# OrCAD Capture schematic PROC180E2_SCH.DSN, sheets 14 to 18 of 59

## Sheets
14 15. SOC POWER SUPPLIES - LDOs: size C; title: SOC POWER SUPPLIES - LDOs  & VCC_3V3_SYS LOAD SWITCH
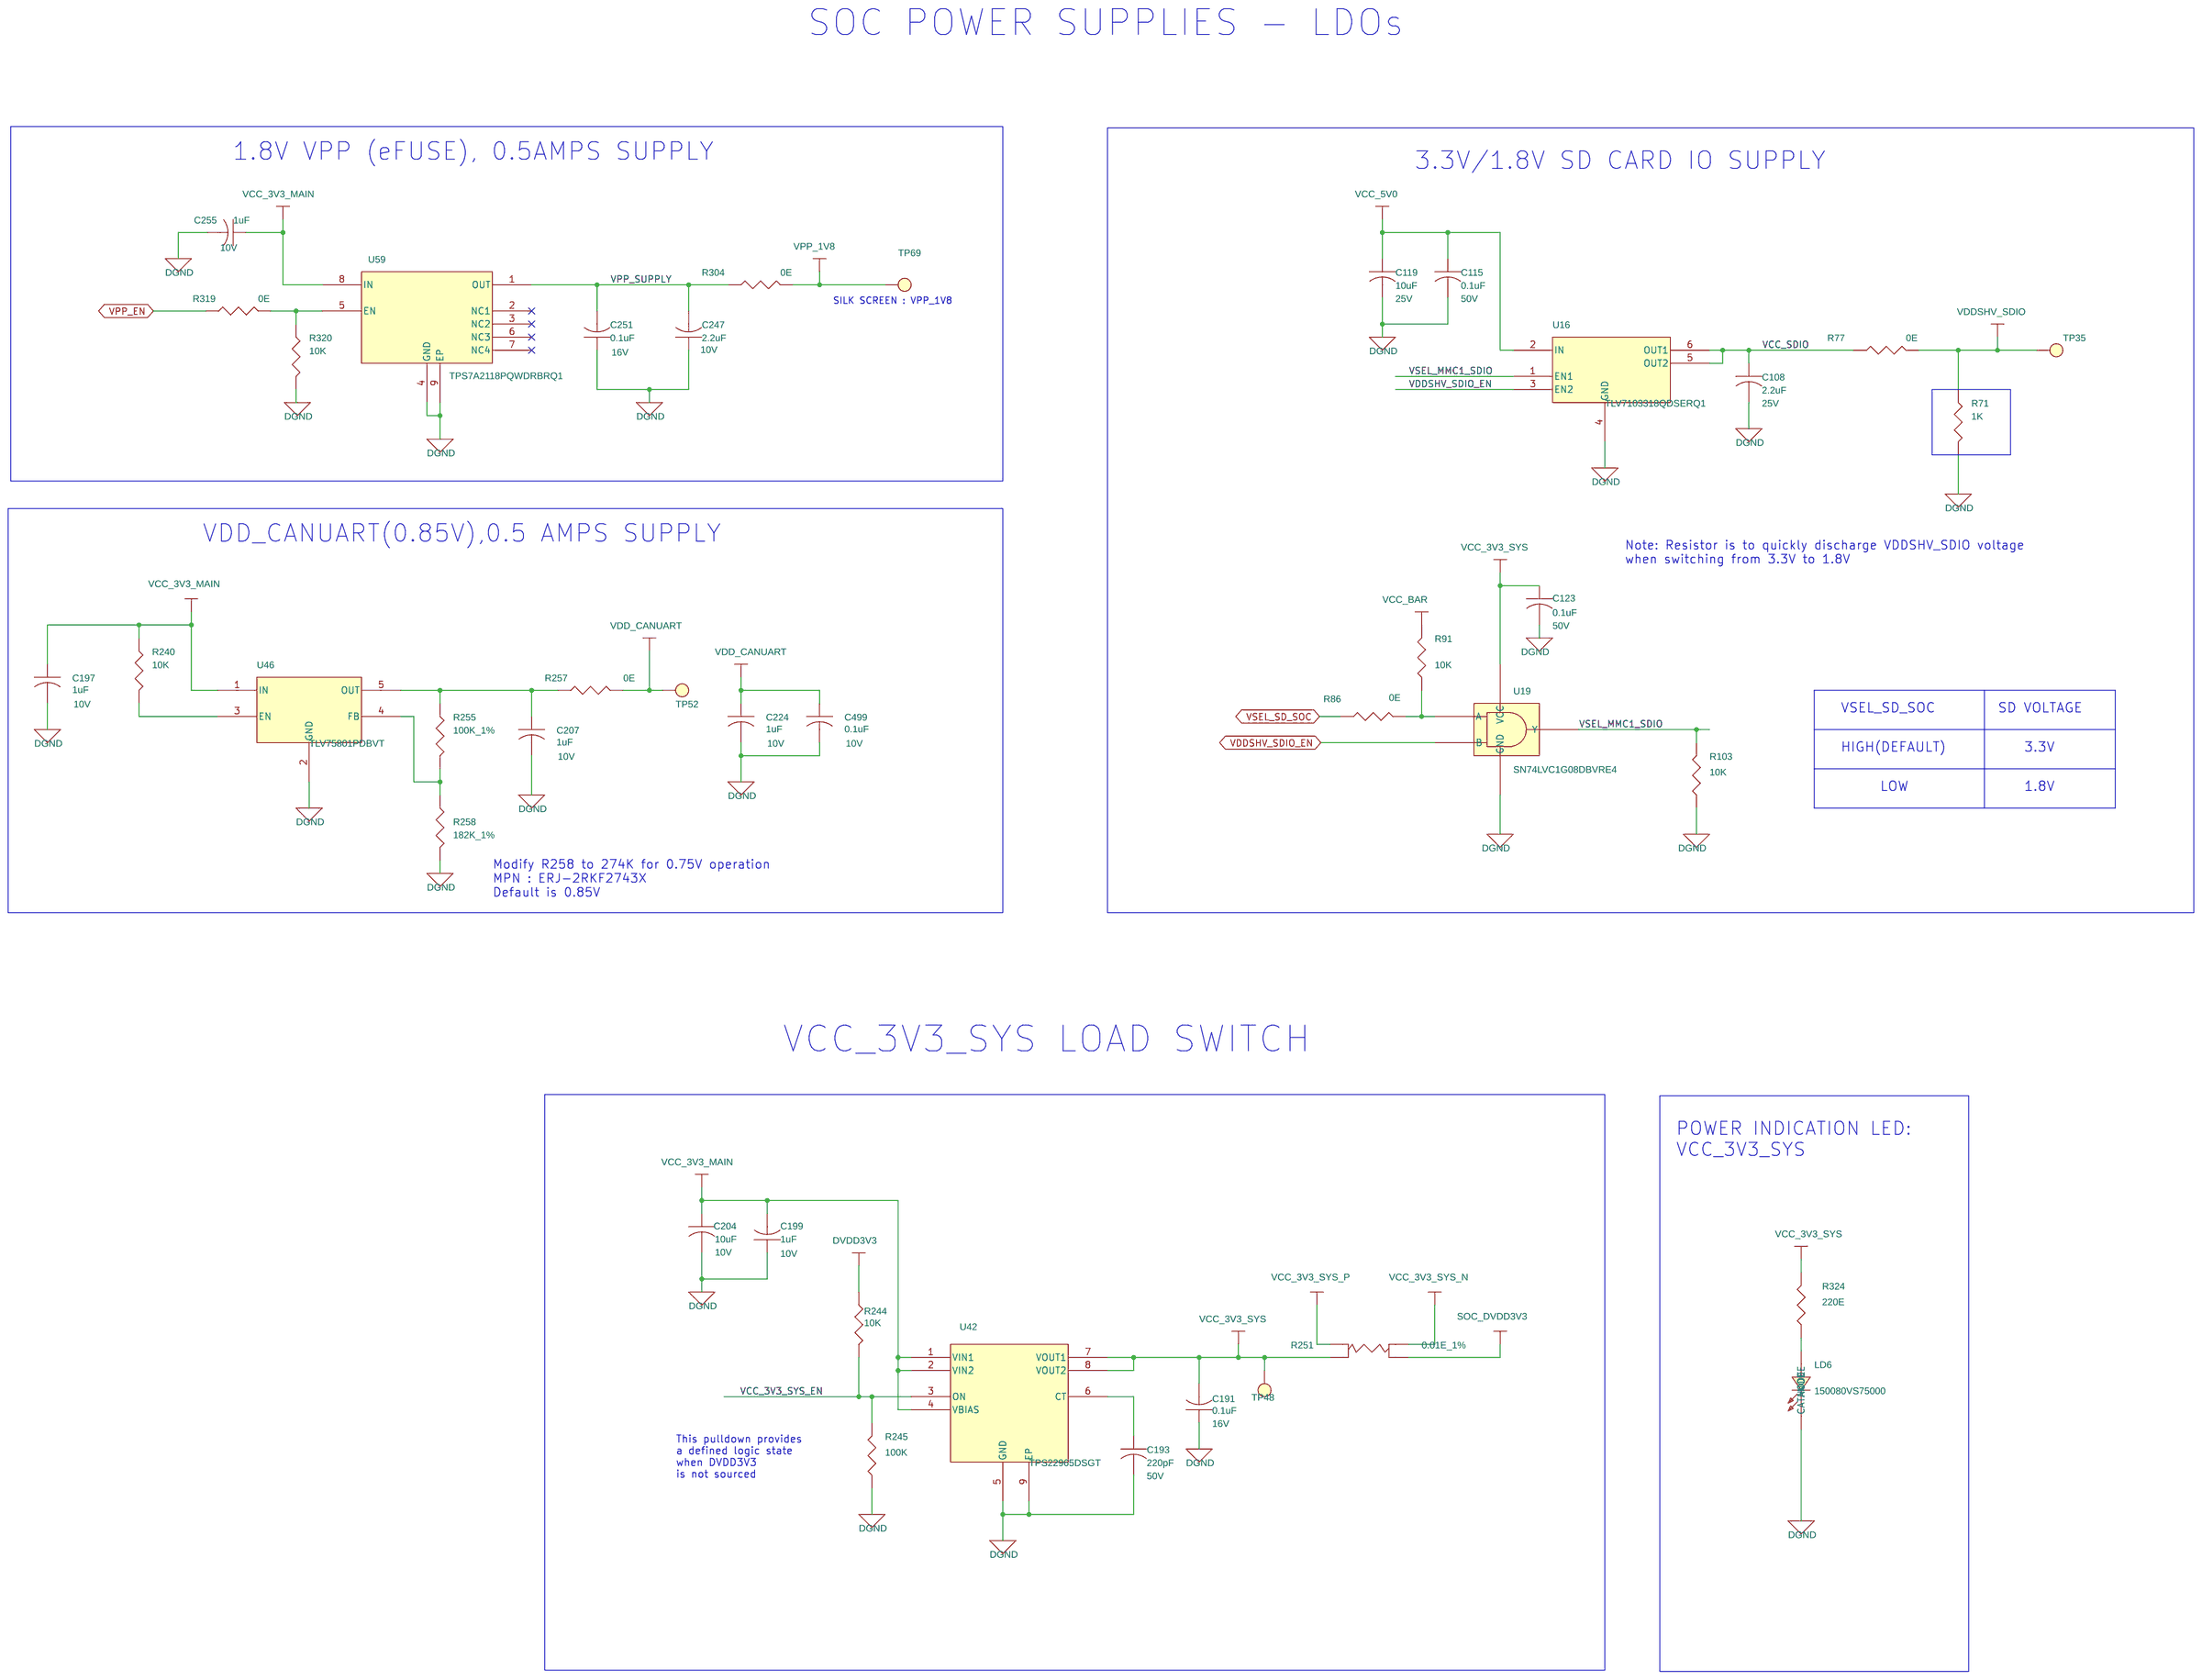
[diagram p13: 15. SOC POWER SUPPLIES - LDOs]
15 03. KEY COLLATERAL REFERENCES: title: LINK TO DESIGN COLLATERALS
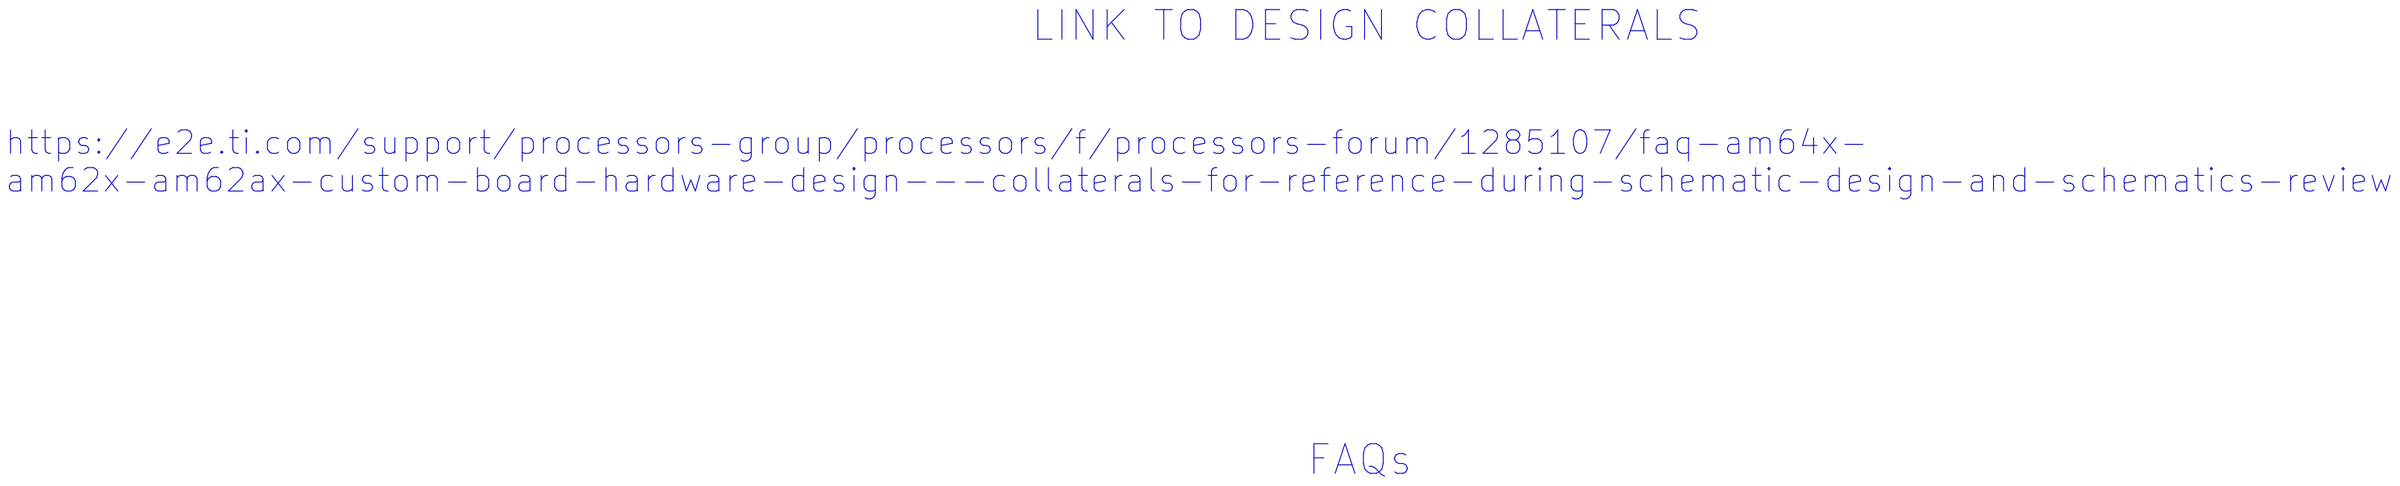
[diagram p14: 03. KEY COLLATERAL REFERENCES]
16 44. PCM6240 BUFFERS: size C; title: PCM6240 BUFFERS
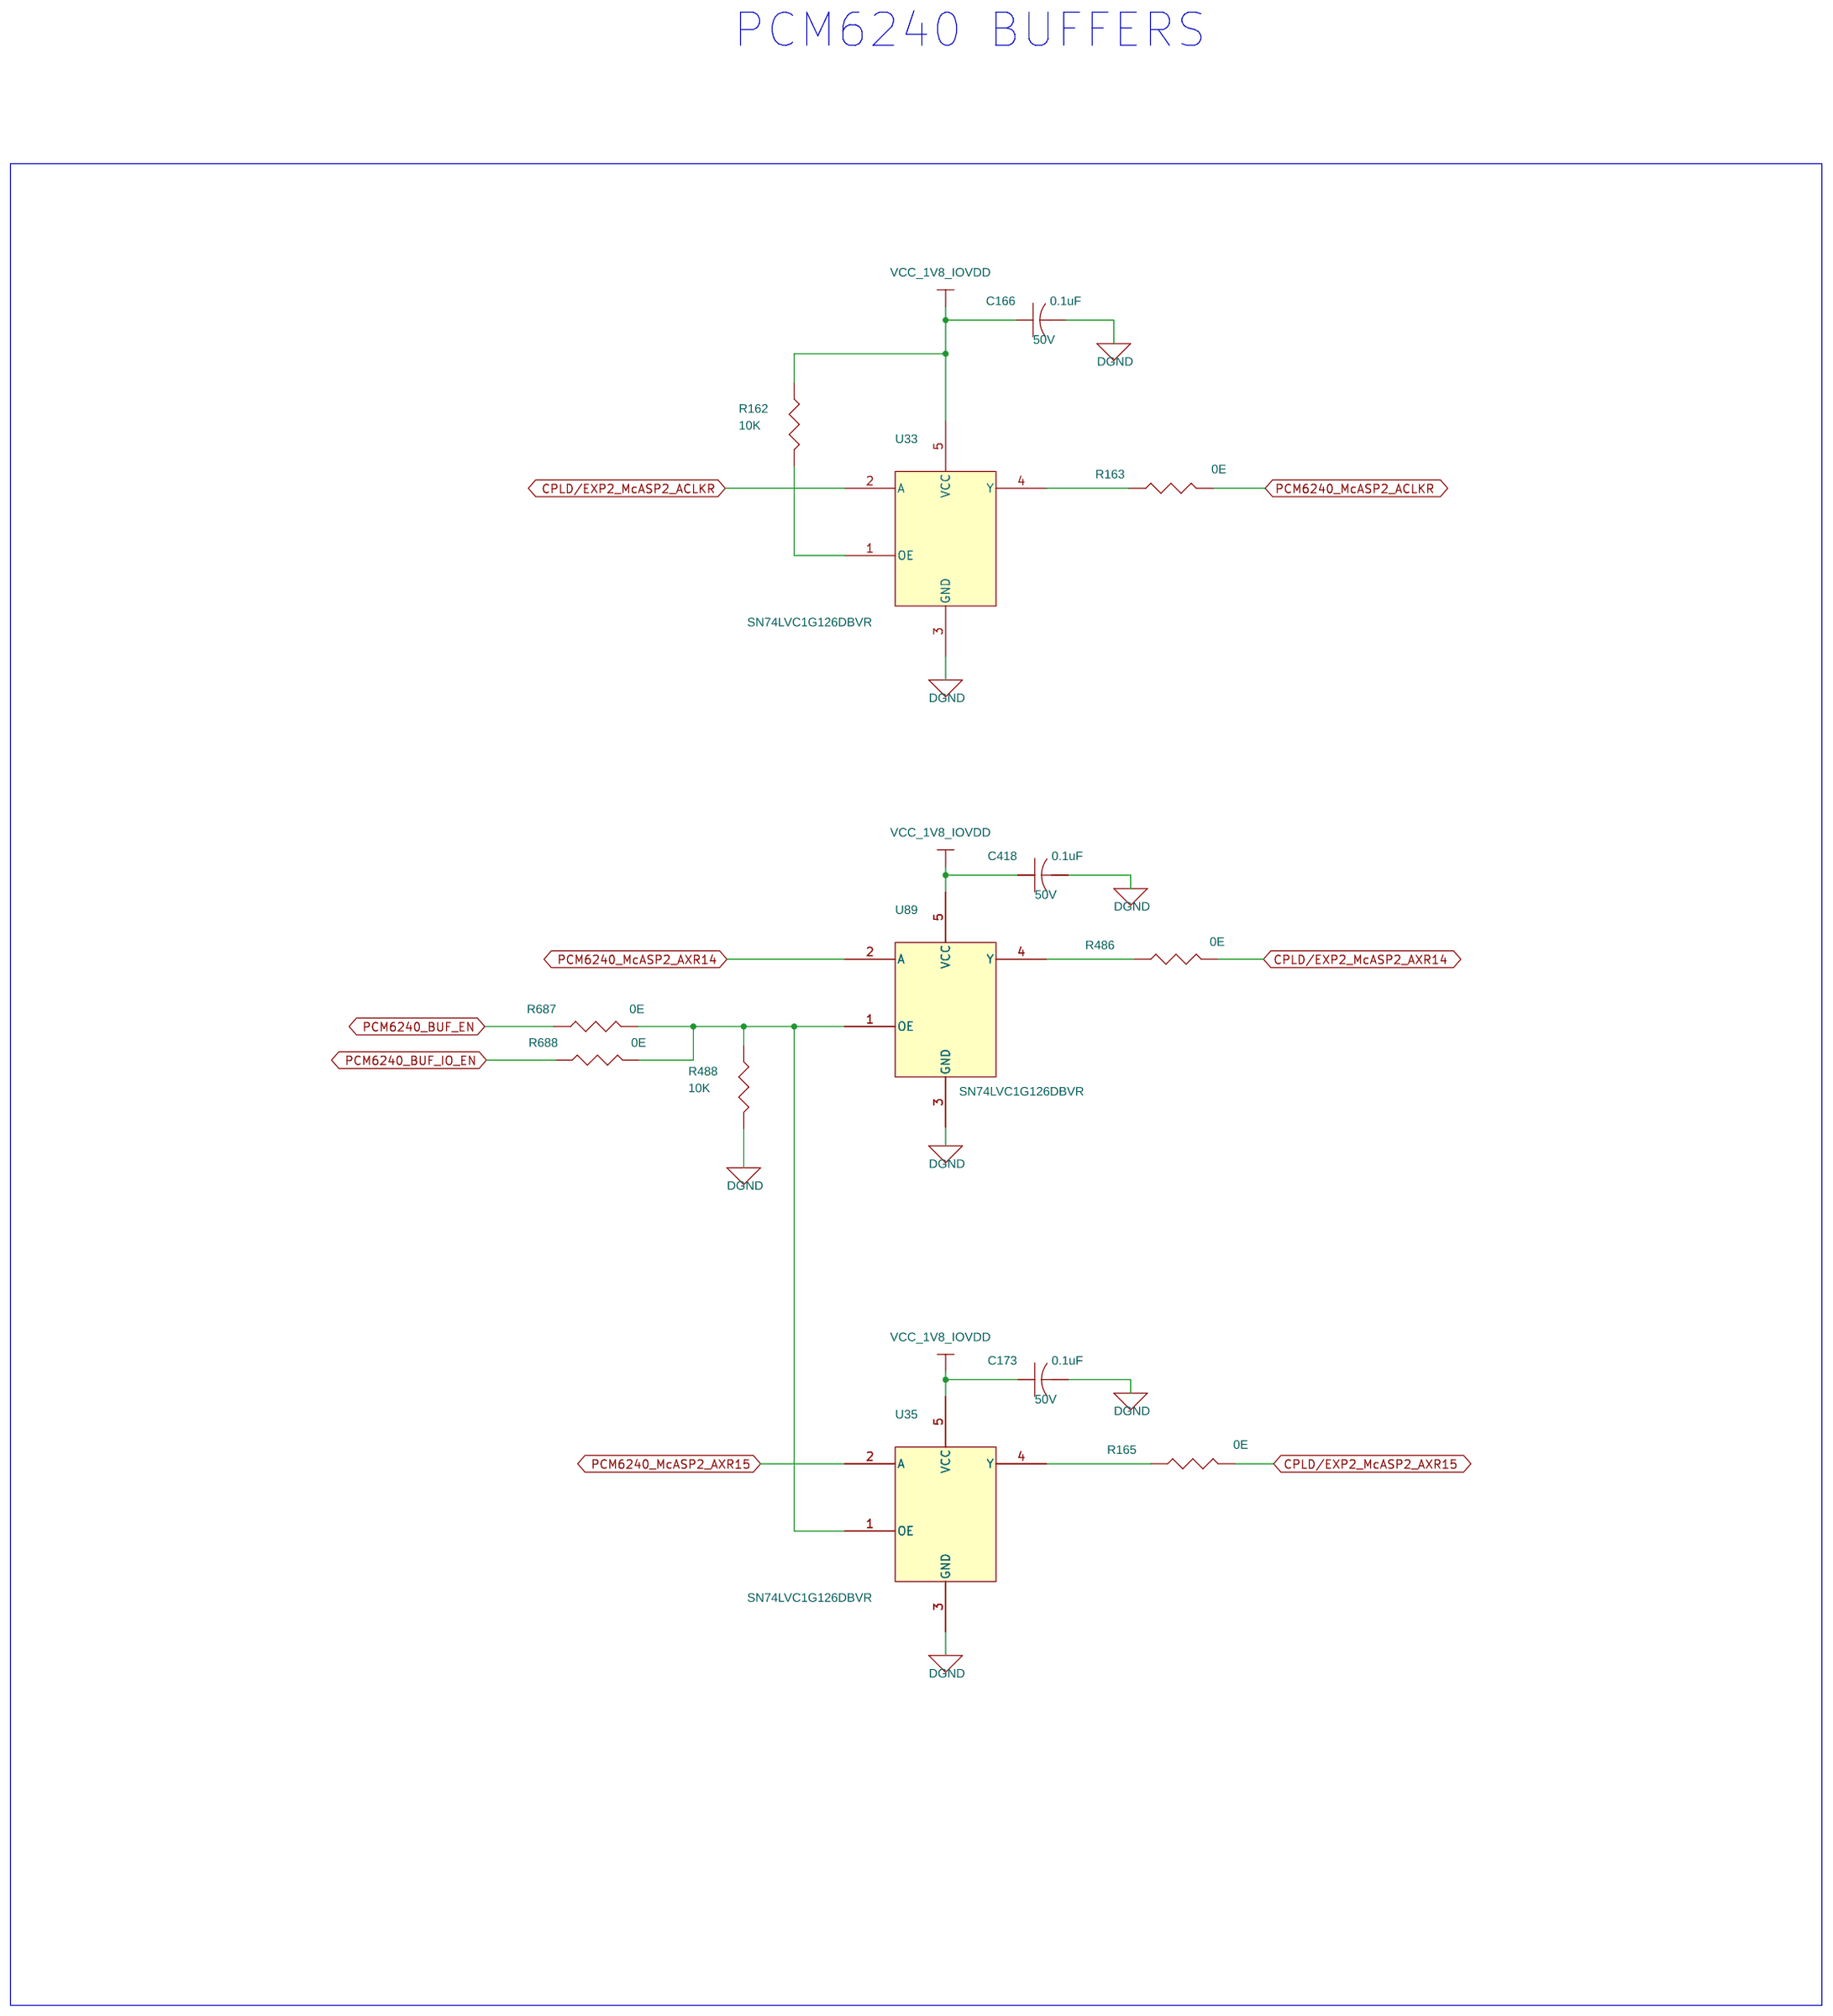
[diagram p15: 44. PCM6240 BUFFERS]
17 50. TEMPERATURE SENSOR & BRD ID: size C; title: TEMPERATURE SENSORS & BOARD ID EEPROM
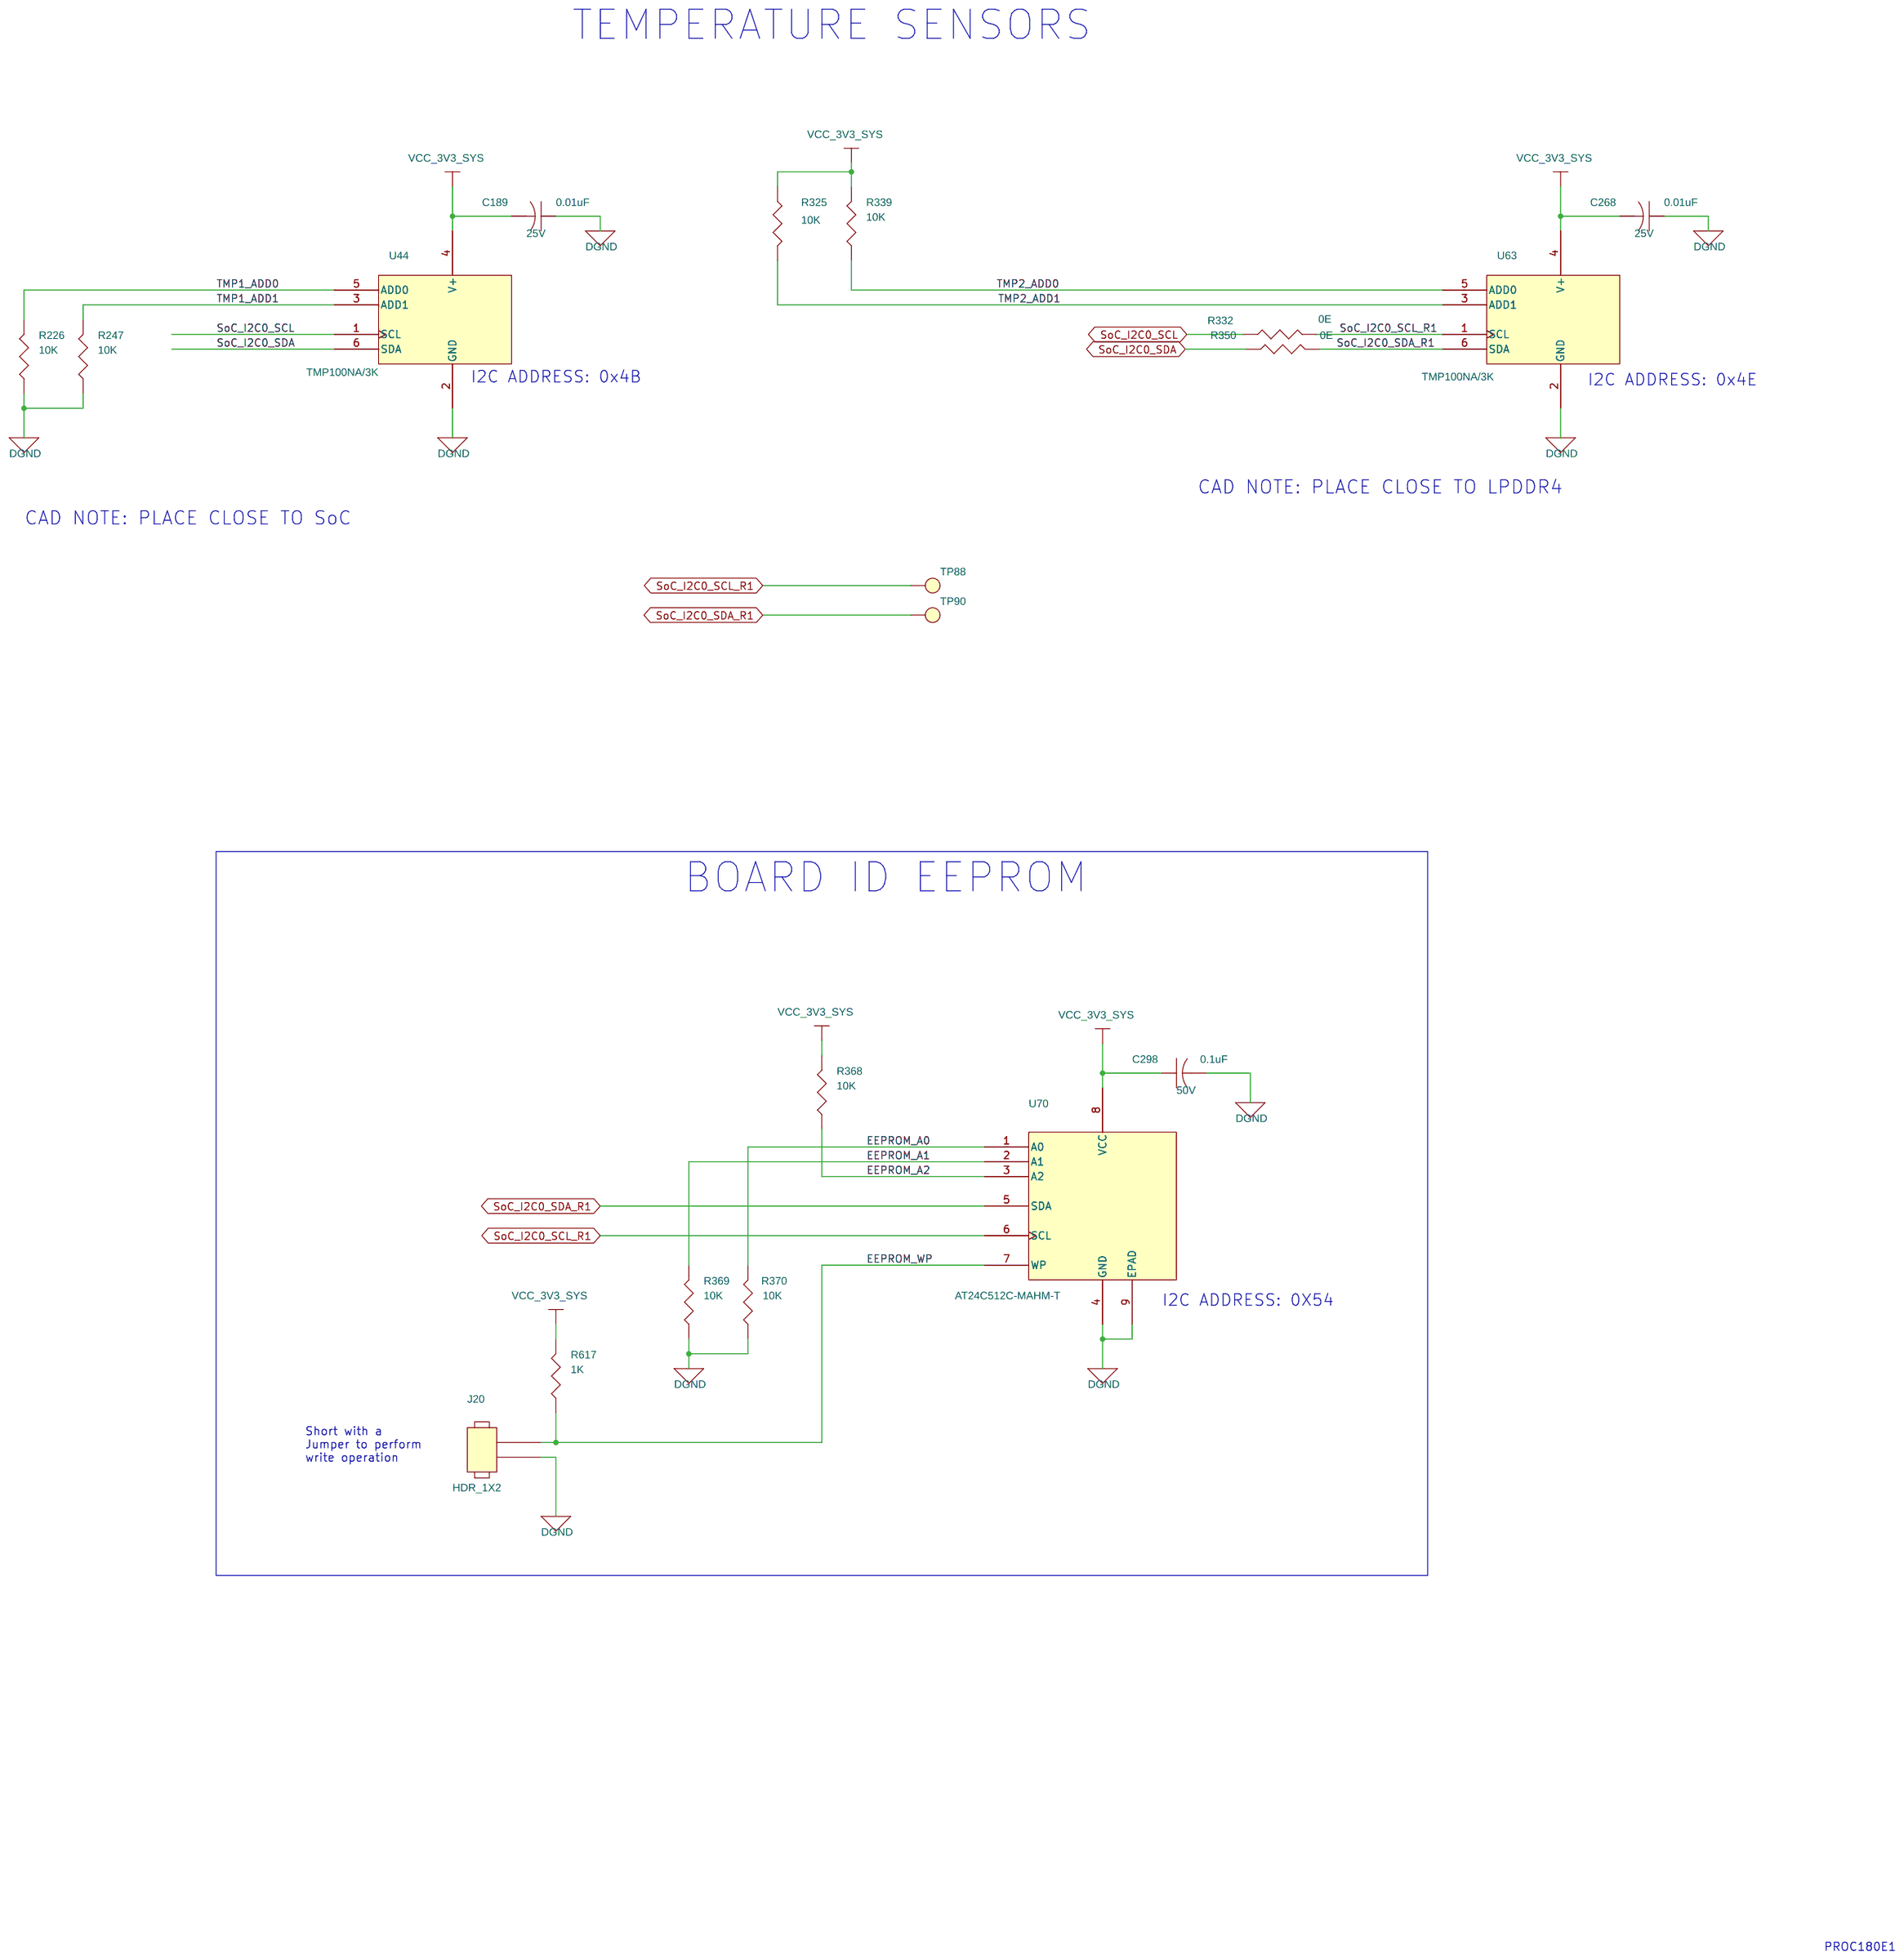
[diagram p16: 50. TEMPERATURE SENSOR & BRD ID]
18 51. CURRENT MONITORING - 1: size C; title: CURRENT MONITORING DEVICES - 1
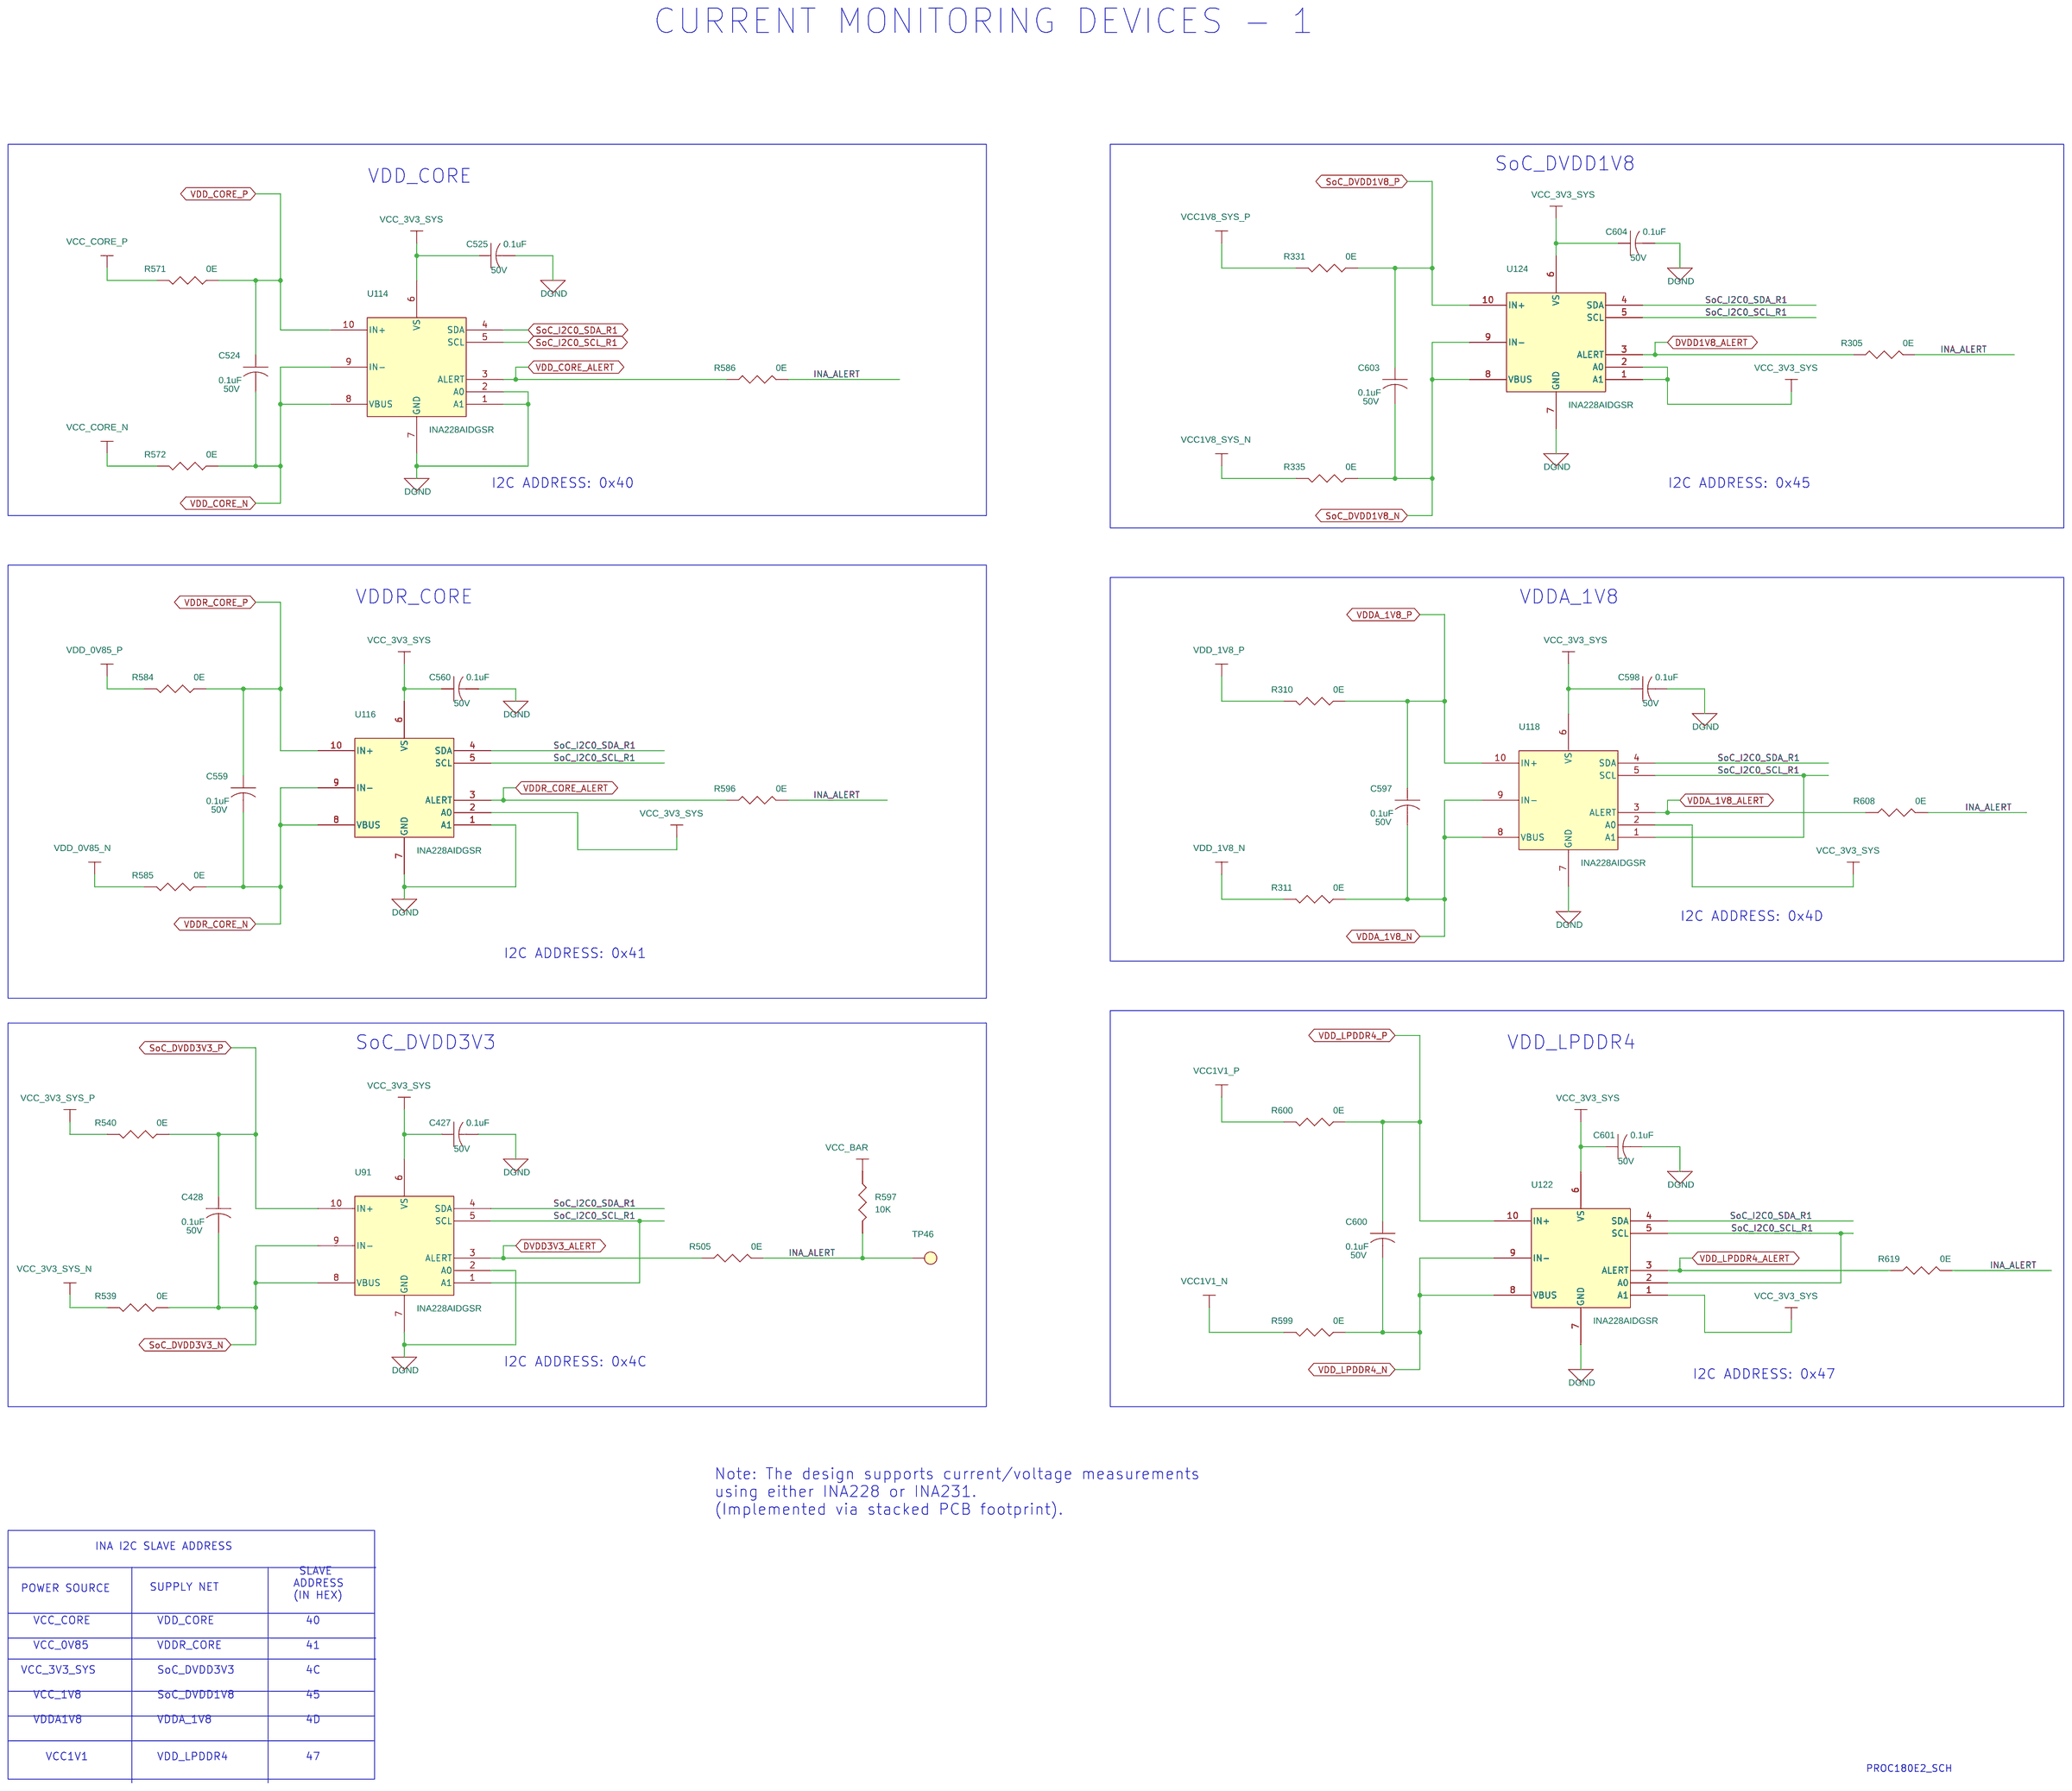
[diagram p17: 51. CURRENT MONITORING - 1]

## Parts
sheet 15. SOC POWER SUPPLIES - LDOs
C108  2.2uF  [CAP0402_0-75]
C115  0.1uF  [CAP0402_0-75]
C119  10uF  [CAP0603_1]
C123  0.1uF  [CAP0402_0-75]
C191  0.1uF  [CAP0201_0-5]
C193  220pF  [CAP0402_0-75]
C197  1uF  [CAP0201_0-5]
C199  1uF  [CAP0201_0-5]
C204  10uF  [CAP0402_0-75]
C207  1uF  [CAP0201_0-5]
C224  1uF  [CAP0201_0-5]
C247  2.2uF  [CAP0201_0-75]
C251  0.1uF  [CAP0201_0-5]
C255  1uF  [CAP0201_0-5]
C499  0.1uF  [CAP0201_0-5]
LD6  150080VS75000  [LED_150080VS75000_80X50_SMD_0-8]
R71  1K  [RES0402_0-5]
R77  0E  [RES0805_0-75]
R86  0E  [RES0805_0-75]
R91  10K  [RES0201_0-5]
R103  10K  [RES0402_0-5]
R240  10K  [RES0201_0-5]
R244  10K  [RES0201_0-5]
R245  100K  [RES0402_0-5]
R251  0.01E_1%  [RES_KRL3216T4_1206-4_0-7]
R255  100K_1%  [RES0402_0-5]
R257  0E  [RES0402_0-5]
R258  182K_1%  [RES0402_0-5]
R304  0E  [RES0603_0-75]
R319  0E  [RES0201_0-5]
R320  10K  [RES0201_0-5]
R324  220E  [RES0402_0-5]
TP35  TP20_SMD  [TP20_SMD]
TP48  TP20_SMD  [TP20_SMD]
TP52  TP20_SMD  [TP20_SMD]
TP69  TP20_SMD  [TP20_SMD]
U16  TLV7103318QDSERQ1  [WSON6_TPS717_60X60_0-8]
U19  SN74LVC1G08DBVRE4  [SOT23-5]
U42  TPS22965DSGT  [WSON8_19-68_80X80_0-8]
U46  TLV75801PDBVT  [SOT23-5_1-5]
U59  TPS7A2118PQWDRBRQ1  [SON8_25-59_130X130_1]
sheet 44. PCM6240 BUFFERS
C166  0.1uF  [CAP0402_0-75]
C173  0.1uF  [CAP0402_0-75]
C418  0.1uF  [CAP0402_0-75]
R162  10K  [RES0201_0-5]
R163  0E  [RES0201_0-5]
R165  0E  [RES0201_0-5]
R486  0E  [RES0201_0-5]
R488  10K  [RES0201_0-5]
R687  0E  [RES0201_0-5]
R688  0E  [RES0201_0-5]
U33  SN74LVC1G126DBVR  [SOT23-5_1-5]
U35  SN74LVC1G126DBVR  [SOT23-5_1-5]
U89  SN74LVC1G126DBVR  [SOT23-5_1-5]
sheet 50. TEMPERATURE SENSOR & BRD ID
C189  0.01uF  [CAP0201_0-5]
C268  0.01uF  [CAP0201_0-5]
C298  0.1uF  [CAP0402_0-75]
J20  HDR_1X2  [HDR_1X2_61300211121_S_T_8-6]
R226  10K  [RES0201_0-5]
R247  10K  [RES0201_0-5]
R325  10K  [RES0201_0-5]
R332  0E  [RES0402_0-5]
R339  10K  [RES0201_0-5]
R350  0E  [RES0402_0-5]
R368  10K  [RES0201_0-5]
R369  10K  [RES0201_0-5]
R370  10K  [RES0201_0-5]
R617  1K  [RES0402_0-5]
TP88  TP20_SMD  [TP20_SMD]
TP90  TP20_SMD  [TP20_SMD]
U44  TMP100NA/3K  [SOT23-6_1-5]
U63  TMP100NA/3K  [SOT23-6_1-5]
U70  AT24C512C-MAHM-T  [UDFN8_19-68_120X80_0-6]
sheet 51. CURRENT MONITORING - 1
C427  0.1uF  [CAP0402_0-75]
C428  0.1uF  [CAP0402_0-75]
C524  0.1uF  [CAP0402_0-75]
C525  0.1uF  [CAP0402_0-75]
C559  0.1uF  [CAP0402_0-75]
C560  0.1uF  [CAP0402_0-75]
C597  0.1uF  [CAP0402_0-75]
C598  0.1uF  [CAP0402_0-75]
C600  0.1uF  [CAP0402_0-75]
C601  0.1uF  [CAP0402_0-75]
C603  0.1uF  [CAP0402_0-75]
C604  0.1uF  [CAP0402_0-75]
R305  0E  [RES0201_0-5]
R310  0E  [RES0402_0-5]
R311  0E  [RES0402_0-5]
R331  0E  [RES0402_0-5]
R335  0E  [RES0402_0-5]
R505  0E  [RES0201_0-5]
R539  0E  [RES0402_0-5]
R540  0E  [RES0402_0-5]
R571  0E  [RES0402_0-5]
R572  0E  [RES0402_0-5]
R584  0E  [RES0402_0-5]
R585  0E  [RES0402_0-5]
R586  0E  [RES0201_0-5]
R596  0E  [RES0201_0-5]
R597  10K  [RES0201_0-5]
R599  0E  [RES0402_0-5]
R600  0E  [RES0402_0-5]
R608  0E  [RES0201_0-5]
R619  0E  [RES0201_0-5]
TP46  TP20_SMD  [TP20_SMD]
U91  INA228AIDGSR  [MSOP10_19-68_120X120_1-1]
U114  INA228AIDGSR  [MSOP10_19-68_120X120_1-1]
U116  INA228AIDGSR  [MSOP10_19-68_120X120_1-1]
U118  INA228AIDGSR  [MSOP10_19-68_120X120_1-1]
U122  INA228AIDGSR  [MSOP10_19-68_120X120_1-1]
U124  INA228AIDGSR  [MSOP10_19-68_120X120_1-1]

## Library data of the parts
C108 = CAP: CAP CERAMIC 2.2uF 25V 10% X5R AUTO 0402; Chkd/date: MANIRAJA/240920; Crtd /date: ALVY/240920; Custom_Duty: 15%; Customs_HS_Code: 85322990; Distributor_name: DIGIKEY; Distributor_part_number: 490-12267-1-ND; Footprint Path: Y:\MIS_DATABASE\Library\ALTIUM_TOOL\PCB_FOOTPRINTS\Altium_Footprint_Lib.PcbLib; Height: 0.70MM; Library Path: Y:\MIS_DATABASE\Library\ALTIUM_TOOL\SCHEMATICS_PARTS\MS_DISCRETE_Library.schlib; Mfr_name: MURATA; Mfr_part_number: GRT155R61E225KE13D; Mistral Part No: 120020090019-R; Package: 0402; Part_type: CAPACITORS\CERAMIC; Project: ECU_RO; RoHS: RoHS; Temperature: -55°C+85°C; Tolerance: 10%; Voltage: 25V; Wattage: NA; Weight: 0.65mg; Datasheet: Y:\MIS_DATABASE\DATASHEETS\CAPACITORS\GRT155R61E225KE13.PDF
C115 C166 C173 C418 = CAP: CAP CERAMIC 0.1uF 50V 10% X7R AUTO 0402; Chkd/date: MANIRAJA/250221; Crtd /date: ALVY/240221; Custom_Duty: 15%; Customs_HS_Code: 85322990; Distributor_name: MOUSER; Distributor_part_number: 81-GRT155R71H104KE1D; Footprint Path: Y:\MIS_DATABASE\Library\ALTIUM_TOOL\PCB_FOOTPRINTS\Altium_Footprint_Lib.PcbLib; Height: 0.55MM; Library Path: Y:\MIS_DATABASE\Library\ALTIUM_TOOL\SCHEMATICS_PARTS\MS_DISCRETE_Library.schlib; Mfr_name: MURATA; Mfr_part_number: GRT155R71H104KE01D; Mistral Part No: 120019030005-R; Package: 0402; Part_type: CAPACITORS\CERAMIC; Project: TI_DRA821 SK EVM BRD; RoHS: RoHS; Temperature: -55°C+125°C; Tolerance: 10%; Voltage: 50V; Wattage: NA; Weight: NA; Datasheet: Y:\MIS_DATABASE\DATASHEETS\CAPACITORS\GRT155R71H104KE01.PDF
C119 = CAP: CAP CERAMIC 10uF 25V 20% X5R AUTO 0603; Chkd/date: PRADEEP/130623; Crtd /date: PRADEEP/130623; Custom_Duty: 15%; Customs_HS_Code: 85322990; Distributor_name: NA; Distributor_part_number: NA; Footprint Path: Y:\MIS_DATABASE\Library\ALTIUM_TOOL\PCB_FOOTPRINTS\Altium_Footprint_Lib.PcbLib; Height: 1.00MM; Library Path: Y:\MIS_DATABASE\Library\ALTIUM_TOOL\SCHEMATICS_PARTS\MS_DISCRETE_Library.schlib; Mfr_name: MURATA; Mfr_part_number: GRT188R61E106ME13; Mistral Part No: 120022060023-R; Package: 0603; Part_type: CAPACITORS\CERAMIC; Project: AM62P_SK; RoHS: RoHS; Temperature: -55°C+85°C; Tolerance: 20%; Voltage: 25V; Wattage: NA; Weight: 2mg; Datasheet: Y:\MIS_DATABASE\DATASHEETS\CAPACITORS\GRT188R61E106ME13.PDF
C123 C298 C427 C428 C524 C525 C559 C560 C597 C598 C600 C601 C603 C604 = CAP: CAP CERAMIC 0.1uF 50V 10% X7R AUTO 0402; Alt_Mfr_name: YAGEO AMERICA; Alt_Mfr_part_number: CC0402KRX5R8BB104; Chkd/date: MANIRAJA/250221; Crtd /date: ALVY/240221; Custom_Duty: 15%; Customs_HS_Code: 85322990; Distributor_name: MOUSER; Distributor_part_number: 81-GRT155R71H104KE1D; Footprint Path: Y:\MIS_DATABASE\Library\ALTIUM_TOOL\PCB_FOOTPRINTS\Altium_Footprint_Lib.PcbLib; Height: 0.55MM; Library Path: Y:\MIS_DATABASE\Library\ALTIUM_TOOL\SCHEMATICS_PARTS\MS_DISCRETE_Library.schlib; Mfr_name: MURATA; Mfr_part_number: GRT155R71H104KE01D; Mistral Part No: 120019030005-R; Package: 0402; Part_type: CAPACITORS\CERAMIC; Project: TI_DRA821 SK EVM BRD; RoHS: RoHS; Temperature: -55°C+125°C; Tolerance: 10%; Voltage: 50V; Wattage: NA; Weight: NA; Datasheet: Y:\MIS_DATABASE\DATASHEETS\CAPACITORS\GRT155R71H104KE01.PDF
C191 C251 = CAP: CAP CERAMIC 0.1uF 16V 10% X7S AUTO 0201; Alt_Mfr_name: YAGEO AMERICA; Alt_Mfr_part_number: CC0402KRX5R8BB104; Chkd/date: MANIRAJA/110321; Crtd /date: ALVY/110321; Custom_Duty: 15%; Customs_HS_Code: 85322990; Distributor_name: DIGIKEY; Distributor_part_number: 490-GRT033C71C104KE01DTR-ND; Footprint Path: Y:\MIS_DATABASE\Library\ALTIUM_TOOL\PCB_FOOTPRINTS\Altium_Footprint_Lib.PcbLib; Height: 0.33MM; Library Path: Y:\MIS_DATABASE\Library\ALTIUM_TOOL\SCHEMATICS_PARTS\MS_DISCRETE_Library.schlib; Mfr_name: MURATA; Mfr_part_number: GRT033C71C104KE01D; Mistral Part No: 120021030007-R; Package: 0201; Part_type: CAPACITORS\CERAMIC; Project: J7ES_SK_BRD; RoHS: RoHS; Temperature: -55°C+125°C; Tolerance: 10%; Voltage: 16V; Wattage: NA; Weight: 330mg; Datasheet: Y:\MIS_DATABASE\DATASHEETS\CAPACITORS\GRT033C71C104KE01.PDF
C193 = CAP: CAP CERAMIC 220pF 50V 5% C0G(NP0) AUTO 0402; Chkd/date: PRADEEP/130623; Crtd /date: PRADEEP/130623; Custom_Duty: 15%; Customs_HS_Code: 85322990; Distributor_name: NA; Distributor_part_number: NA; Footprint Path: Y:\MIS_DATABASE\Library\ALTIUM_TOOL\PCB_FOOTPRINTS\Altium_Footprint_Lib.PcbLib; Height: 0.55MM; Library Path: Y:\MIS_DATABASE\Library\ALTIUM_TOOL\SCHEMATICS_PARTS\MS_DISCRETE_Library.schlib; Mfr_name: MURATA; Mfr_part_number: GRT1555C1H221JA02; Mistral Part No: 120022060024-R; Package: 0402; Part_type: CAPACITORS\CERAMIC; Project: AM62P_SK; RoHS: RoHS; Temperature: -55°C+125°C; Tolerance: 5%; Voltage: 50V; Wattage: NA; Weight: 3.1mg; Datasheet: Y:\MIS_DATABASE\DATASHEETS\CAPACITORS\GRT1555C1H221JA02.PDF
C197 C207 C224 = CAP: CAP CERAMIC 1uF 10V 20% X5R 0201; Chkd/date: NAVEED/070415; Crtd /date: VASANTHA/230314; Custom_Duty: 15%; Customs_HS_Code: 85322990; Distributor_name: DIGIKEY; Distributor_part_number: 1276-1324-1-ND; Footprint Path: Y:\MIS_DATABASE\Library\ALTIUM_TOOL\PCB_FOOTPRINTS\Altium_Footprint_Lib.PcbLib; Height: 0.35MM; Library Path: Y:\MIS_DATABASE\Library\ALTIUM_TOOL\SCHEMATICS_PARTS\MS_DISCRETE_Library.schlib; Mfr_name: SAMSUNG; Mfr_part_number: CL03A105MP3NSNC; Mistral Part No: 120015030003-R; Package: 0201; Part_type: CAPACITORS\CERAMIC; Project: DUET BOARDS; RoHS: RoHS; Temperature: -55°C+85°C; Tolerance: 20%; Voltage: 10V; Wattage: NA; Weight: 0.17mg; Datasheet: Y:\MIS_DATABASE\DATASHEETS\CAPACITORS\CL03A105MP3NSNC.PDF
C199 C255 = CAP: CAP CERAMIC 1uF 10V 20% X6S 0201; Chkd/date: PRADEEP/130623; Crtd /date: PRADEEP/130623; Custom_Duty: 15%; Customs_HS_Code: 85322990; Distributor_name: DIGIKEY; Distributor_part_number: 490-GRT033C81A105ME13DTR-ND; Footprint Path: Y:\MIS_DATABASE\Library\ALTIUM_TOOL\PCB_FOOTPRINTS\Altium_Footprint_Lib.PcbLib; Height: 0.39MM; Library Path: Y:\MIS_DATABASE\Library\ALTIUM_TOOL\SCHEMATICS_PARTS\MS_DISCRETE_Library.schlib; Mfr_name: MURATA; Mfr_part_number: GRT033C81A105ME13D; Mistral Part No: 120022060020-R; Package: 0201; Part_type: CAPACITORS\CERAMIC; Project: AM62P_SK; RoHS: RoHS; Temperature: -55°C+105°C; Tolerance: 20%; Voltage: 10V; Wattage: NA; Weight: NA; Datasheet: Y:\MIS_DATABASE\DATASHEETS\CAPACITORS\GRT033C81A105ME13D.PDF
C204 = CAP: CAP CERAMIC 10uF 10V 20% X5R 0402; Chkd/date: PRADEEP/130623; Crtd /date: PRADEEP/130623; Custom_Duty: 15%; Customs_HS_Code: 85322990; Distributor_name: NA; Distributor_part_number: NA; Footprint Path: Y:\MIS_DATABASE\Library\ALTIUM_TOOL\PCB_FOOTPRINTS\Altium_Footprint_Lib.PcbLib; Height: 0.55MM; Library Path: Y:\MIS_DATABASE\Library\ALTIUM_TOOL\SCHEMATICS_PARTS\MS_DISCRETE_Library.schlib; Mfr_name: MURATA; Mfr_part_number: GRM155R61A106ME18; Mistral Part No: 120022060018-R; Package: 0402; Part_type: CAPACITORS\CERAMIC; Project: AM62P_SK; RoHS: RoHS; Temperature: -55°C+85°C; Tolerance: 20%; Voltage: 10V; Wattage: NA; Weight: 6mg; Datasheet: Y:\MIS_DATABASE\DATASHEETS\CAPACITORS\MURATA-GXX-SER_NOV17.PDF
C247 = CAP: CAP CERAMIC 2.2uF 10V 20% X5R 0201; Chkd/date: PRADEEP/130623; Crtd /date: PRADEEP/130623; Custom_Duty: 15%; Customs_HS_Code: 85322990; Distributor_name: NA; Distributor_part_number: NA; Footprint Path: Y:\MIS_DATABASE\Library\ALTIUM_TOOL\PCB_FOOTPRINTS\Altium_Footprint_Lib.PcbLib; Height: 0.55MM; Library Path: Y:\MIS_DATABASE\Library\ALTIUM_TOOL\SCHEMATICS_PARTS\MS_DISCRETE_Library.schlib; Mfr_name: MURATA; Mfr_part_number: GRM035R61A225ME01; Mistral Part No: 120022060026-R; Package: 0201; Part_type: CAPACITORS\CERAMIC; Project: AM62P_SK; RoHS: RoHS; Temperature: -55°C+85°C; Tolerance: 20%; Voltage: 10V; Wattage: NA; Weight: 0.57mg; Datasheet: Y:\MIS_DATABASE\DATASHEETS\CAPACITORS\GRM035R61A225ME01.PDF
C499 = CAP: CAP CERAMIC 0.1uF 10V 10% X5R 0201; Chkd/date: MANIRAJA/290421; Crtd /date: ALVY/290421; Custom_Duty: 15%; Customs_HS_Code: 85322990; Distributor_name: DIGIKEY; Distributor_part_number: 1276-1115-1-ND; Footprint Path: Y:\MIS_DATABASE\Library\ALTIUM_TOOL\PCB_FOOTPRINTS\Altium_Footprint_Lib.PcbLib; Height: 0.33MM; Library Path: Y:\MIS_DATABASE\Library\ALTIUM_TOOL\SCHEMATICS_PARTS\MS_DISCRETE_Library.schlib; Mfr_name: SAMSUNG; Mfr_part_number: CL03A104KP3NNNC; Mistral Part No: 120009050017-R; Package: 0201; Part_type: CAPACITORS\CERAMIC; Project: SRMS-SAR_BRD; RoHS: RoHS; Temperature: -55°C+85°C; Tolerance: 10%; Voltage: 10V; Wattage: NA; Weight: 0.33mg; Datasheet: Y:\MIS_DATABASE\DATASHEETS\CAPACITORS\CL03A104KP3NNNC.PDF
LD6 = DIODE_LED: DIODE LED BRIGHT GREEN SMD; Chkd/date: MANIRAJA/180820; Crtd /date: ALVY/180820; Custom_Duty: 24%; Customs_HS_Code: 85439000; Distributor_name: DIGIKEY; Distributor_part_number: 732-4986-1-ND; Footprint Path: Y:\MIS_DATABASE\Library\ALTIUM_TOOL\PCB_FOOTPRINTS\Altium_Footprint_Lib.PcbLib; Height: 0.80MM; Library Path: Y:\MIS_DATABASE\Library\ALTIUM_TOOL\SCHEMATICS_PARTS\MS_OPTO_Library.schlib; Mfr_name: WURTH ELECTRONICS; Mistral Part No: 130020080012-R; Package: SMD; Part_type: OPTO\LED; Project: AM64x_EVM_BRD; RoHS: RoHS; Temperature: -40°C+85°C; Tolerance: NA; Voltage: NA; Wattage: NA; Weight: 10mg; Datasheet: Y:\MIS_DATABASE\DATASHEETS\DISCRETES\LEDS\150080VS75000.PDF
R71 R617 = RESISTOR: RES 1K 1/10W 5% 0402; Chkd/date: VASANTHA/201216; Crtd /date: MAZHAR/230805; Custom_Duty: 15%; Customs_HS_Code: 85332119; Distributor_name: DIGIKEY; Distributor_part_number: P1.0KJCT-ND; Footprint Path: Y:\MIS_DATABASE\Library\ALTIUM_TOOL\PCB_FOOTPRINTS\Altium_Footprint_Lib.PcbLib; Height: 0.40MM; Library Path: Y:\MIS_DATABASE\Library\ALTIUM_TOOL\SCHEMATICS_PARTS\MS_DISCRETE_Library.schlib; Mfr_name: PANASONIC-ECG; Mfr_part_number: ERJ-2GEJ102X; Mistral Part No: 110009030400-R; Package: 0402; Part_type: RESISTORS\FIXED; Project: HSE; RoHS: RoHS; Temperature: -55°C+155°C; Tolerance: 5%; Voltage: NA; Wattage: 1/10W; Weight: 0.8mg; Datasheet: Y:\MIS_DATABASE\DATASHEETS\RESISTORS\PAN-ERJSER_NOV17.PDF
R77 R86 = RESISTOR: RES 0E 1/8W 5% 0805; Chkd/date: VASANTHA/130416; Crtd /date: JEBRAN/020316; Custom_Duty: 15%; Customs_HS_Code: 85332119; Distributor_name: DIGIKEY; Distributor_part_number: 311-0.0ARCT-ND; Footprint Path: Y:\MIS_DATABASE\Library\ALTIUM_TOOL\PCB_FOOTPRINTS\Altium_Footprint_Lib.PcbLib; Height: 0.60MM; Library Path: Y:\MIS_DATABASE\Library\ALTIUM_TOOL\SCHEMATICS_PARTS\MS_DISCRETE_Library.schlib; Mfr_name: YAGEO AMERICA; Mfr_part_number: RC0805JR-070RL; Mistral Part No: 110009030074-R; Package: 0805; Part_type: RESISTORS\FIXED; Project: ZK_BIOMETRIC; RoHS: RoHS; Temperature: -55°C+155°C; Tolerance: 5%; Voltage: NA; Wattage: 1/8W; Weight: 5.5mg; Datasheet: Y:\MIS_DATABASE\DATASHEETS\RESISTORS\RCXXXXL-SER_MAR18.PDF
R91 R162 R226 R240 R244 R247 R320 R325 R339 R368-R370 R488 R597 = RESISTOR: RES 10K 1/20W 5% 0201; Chkd/date: MANIRAJA/050517; Crtd /date: MANIRAJA/050517; Custom_Duty: 15%; Customs_HS_Code: 85332119; Distributor_name: DIGIKEY; Distributor_part_number: 311-10KNCT-ND; Footprint Path: Y:\MIS_DATABASE\Library\ALTIUM_TOOL\PCB_FOOTPRINTS\Altium_Footprint_Lib.PcbLib; Height: 0.26MM; Library Path: Y:\MIS_DATABASE\Library\ALTIUM_TOOL\SCHEMATICS_PARTS\MS_DISCRETE_Library.schlib; Mfr_name: YAGEO AMERICA; Mfr_part_number: RC0201JR-0710KL; Mistral Part No: 110010070051-R; Package: 0201; Part_type: RESISTORS\FIXED; Project: GOLDEN-I LITE; RoHS: RoHS; Temperature: -55°C+125°C; Tolerance: 5%; Voltage: NA; Wattage: 1/20W; Weight: 0.17mg; Datasheet: Y:\MIS_DATABASE\DATASHEETS\RESISTORS\RCXXXXL-SER_MAR18.PDF
R103 = RESISTOR: RES 10K 1/16W 5% 0402; Chkd/date: VASANTHA/061216; Crtd /date: MAZHAR/230805; Custom_Duty: 15%; Customs_HS_Code: 85332119; Distributor_name: DIGIKEY; Distributor_part_number: 311-10KJRCT-ND; Footprint Path: Y:\MIS_DATABASE\Library\ALTIUM_TOOL\PCB_FOOTPRINTS\Altium_Footprint_Lib.PcbLib; Height: 0.40MM; Library Path: Y:\MIS_DATABASE\Library\ALTIUM_TOOL\SCHEMATICS_PARTS\MS_DISCRETE_Library.schlib; Mfr_name: YAGEO AMERICA; Mfr_part_number: RC0402JR-0710KL; Mistral Part No: 110011060021-R; Package: 0402; Part_type: RESISTORS\FIXED; Project: HSE; RoHS: RoHS; Temperature: -55°C+155°C; Tolerance: 5%; Voltage: NA; Wattage: 1/16W; Weight: 0.65mg; Datasheet: Y:\MIS_DATABASE\DATASHEETS\RESISTORS\RCXXXXL-SER_MAR18.PDF
R245 = RESISTOR: RES 100K 1/10W 5% 0402; Chkd/date: VASANTHA/291216; Crtd /date: GEETHA/190406; Custom_Duty: 15%; Customs_HS_Code: 85332119; Distributor_name: DIGIKEY; Distributor_part_number: P100KJCT-ND; Footprint Path: Y:\MIS_DATABASE\Library\ALTIUM_TOOL\PCB_FOOTPRINTS\Altium_Footprint_Lib.PcbLib; Height: 0.40MM; Library Path: Y:\MIS_DATABASE\Library\ALTIUM_TOOL\SCHEMATICS_PARTS\MS_DISCRETE_Library.schlib; Mfr_name: PANASONIC-ECG; Mfr_part_number: ERJ-2GEJ104X; Mistral Part No: 110009030177-R; Package: 0402; Part_type: RESISTORS\FIXED; Project: RED EYE; RoHS: RoHS; Temperature: -55°C+155°C; Tolerance: 5%; Voltage: NA; Wattage: 1/10W; Weight: 0.8mg; Datasheet: Y:\MIS_DATABASE\DATASHEETS\RESISTORS\PAN-ERJSER_NOV17.PDF
R251 = RESISTOR-4TERM: RES 0.01E 1W 1% 1206-4; Chkd/date: MANIRAJA/060318; Crtd /date: MANIRAJA/060318; Custom_Duty: 15%; Customs_HS_Code: 85332119; Distributor_name: DIGIKEY; Distributor_part_number: 408-1974-1-ND; Footprint Path: Y:\MIS_DATABASE\Library\ALTIUM_TOOL\PCB_FOOTPRINTS\Altium_Footprint_Lib.PcbLib; Height: 0.70MM; Library Path: Y:\MIS_DATABASE\Library\ALTIUM_TOOL\SCHEMATICS_PARTS\MS_DISCRETE_Library.schlib; Mfr_name: SUSUMU; Mfr_part_number: KRL3216T4A-M-R010-F-T1; Mistral Part No: 110018030003-R; Package: 1206-4; Part_type: RESISTORS\FIXED; Project: GRACO SMART MODULE; RoHS: RoHS; Temperature: -55°C+155°C; Tolerance: 1%; Voltage: NA; Wattage: 1W; Weight: 16.2mg; Datasheet: Y:\MIS_DATABASE\DATASHEETS\RESISTORS\KRL-SERIES.PDF
R255 = RESISTOR: RES 100K 1/10W 1% 0402; Chkd/date: VASANTHA/201216; Crtd /date: MAZHAR/130306; Custom_Duty: 15%; Customs_HS_Code: 85332119; Distributor_name: DIGIKEY; Distributor_part_number: P100KLCT-ND; Footprint Path: Y:\MIS_DATABASE\Library\ALTIUM_TOOL\PCB_FOOTPRINTS\Altium_Footprint_Lib.PcbLib; Height: 0.40MM; Library Path: Y:\MIS_DATABASE\Library\ALTIUM_TOOL\SCHEMATICS_PARTS\MS_DISCRETE_Library.schlib; Mfr_name: PANASONIC-ECG; Mfr_part_number: ERJ-2RKF1003X; Mistral Part No: 110009030187-R; Package: 0402; Part_type: RESISTORS\FIXED; Project: J32; RoHS: RoHS; Temperature: -55°C+155°C; Tolerance: 1%; Voltage: NA; Wattage: 1/10W; Weight: 0.8mg; Datasheet: Y:\MIS_DATABASE\DATASHEETS\RESISTORS\PAN-ERJSER_NOV17.PDF
R257 R332 R350 = RESISTOR: RES 0E 1/10W JUMPER 0402; Chkd/date: VASANTHA/061216; Crtd /date: NAVEED/201014; Custom_Duty: 15%; Customs_HS_Code: 85332119; Distributor_name: DIGIKEY; Distributor_part_number: P0.0JCT-ND; Footprint Path: Y:\MIS_DATABASE\Library\ALTIUM_TOOL\PCB_FOOTPRINTS\Altium_Footprint_Lib.PcbLib; Height: 0.40MM; IBISSP_MODLES: VALUE REPEATING 2 TIME; Library Path: Y:\MIS_DATABASE\Library\ALTIUM_TOOL\SCHEMATICS_PARTS\MS_DISCRETE_Library.schlib; Mfr_name: PANASONIC-ECG; Mfr_part_number: ERJ-2GE0R00X; Mistral Part No: 110018030052-R; Package: 0402; Part_type: RESISTORS\FIXED; Project: AEGIS POM; RoHS: RoHS; Temperature: -55°C+155°C; Tolerance: NA; Voltage: NA; Wattage: 1/10W; Weight: 0.8mg; Datasheet: Y:\MIS_DATABASE\DATASHEETS\RESISTORS\PAN-ERJSER_NOV17.PDF
R258 = RESISTOR: RES 182K 1/16W 1% 0402; Chkd/date: ALVY/210122; Crtd /date: TAMILARASU/210122; Custom_Duty: 15%; Customs_HS_Code: 85332119; Distributor_name: DIGIKEY; Distributor_part_number: YAG3015CT-ND; Footprint Path: Y:\MIS_DATABASE\Library\ALTIUM_TOOL\PCB_FOOTPRINTS\Altium_Footprint_Lib.PcbLib; Height: 0.40MM; Library Path: Y:\MIS_DATABASE\Library\ALTIUM_TOOL\SCHEMATICS_PARTS\MS_DISCRETE_Library.schlib; Mfr_name: YAGEO AMERICA; Mfr_part_number: RC0402FR-07182KL; Mistral Part No: 110022010016-R; Package: 0402; Part_type: RESISTORS\FIXED; Project: DLRL DIGITAL RECEIVER_BRD; RoHS: RoHS; Temperature: -55°C+155°C; Tolerance: 1%; Voltage: NA; Wattage: 1/16W; Weight: 0.65mg; Datasheet: Y:\MIS_DATABASE\DATASHEETS\RESISTORS\RCXXXXL-SER_MAR18.PDF
R304 = RESISTOR: RES 0E 1/10W 5% 0603; Chkd/date: MANIRAJA/051217; Crtd /date: BAVISH/180211; Custom_Duty: 15%; Customs_HS_Code: 85332119; Distributor_name: DIGIKEY; Distributor_part_number: 311-0.0GRCT-ND; Footprint Path: Y:\MIS_DATABASE\Library\ALTIUM_TOOL\PCB_FOOTPRINTS\Altium_Footprint_Lib.PcbLib; Height: 0.55MM; Library Path: Y:\MIS_DATABASE\Library\ALTIUM_TOOL\SCHEMATICS_PARTS\MS_DISCRETE_Library.schlib; Mfr_name: YAGEO AMERICA; Mfr_part_number: RC0603JR-070RL; Mistral Part No: 110011020013-R; Package: 0603; Part_type: RESISTORS\FIXED; Project: KENNEL; RoHS: RoHS; Temperature: -55°C+155°C; Tolerance: 5%; Voltage: NA; Wattage: 1/10W; Weight: 2mg; Datasheet: Y:\MIS_DATABASE\DATASHEETS\RESISTORS\RCXXXXL-SER_MAR18.PDF
R163 R165 R305 R319 R486 R505 R586 R596 R608 R619 R687 R688 = RESISTOR: RES 0E 1/20W 5% 0201; Chkd/date: NAVEED/301214; Crtd /date: MUDDU/120710; Custom_Duty: 15%; Customs_HS_Code: 85332119; Distributor_name: DIGIKEY; Distributor_part_number: 311-0.0NCT-ND; Footprint Path: Y:\MIS_DATABASE\Library\ALTIUM_TOOL\PCB_FOOTPRINTS\Altium_Footprint_Lib.PcbLib; Height: 0.26MM; Library Path: Y:\MIS_DATABASE\Library\ALTIUM_TOOL\SCHEMATICS_PARTS\MS_DISCRETE_Library.schlib; Mfr_name: YAGEO AMERICA; Mfr_part_number: RC0201JR-070RL; Mistral Part No: 110010070067-R; Package: 0201; Part_type: RESISTORS\FIXED; Project: PB_BUGBASE; RoHS: RoHS; Temperature: -55°C+125°C; Tolerance: 5%; Voltage: NA; Wattage: 1/20W; Weight: 0.17mg; Datasheet: Y:\MIS_DATABASE\DATASHEETS\RESISTORS\RCXXXXL-SER_MAR18.PDF
R324 = RESISTOR: RES 220E 1/10W 5% 0402; Chkd/date: VASANTHA/291216; Crtd /date: GEETHA/260406; Custom_Duty: 15%; Customs_HS_Code: 85332119; Distributor_name: DIGIKEY; Distributor_part_number: P220JCT-ND; Footprint Path: Y:\MIS_DATABASE\Library\ALTIUM_TOOL\PCB_FOOTPRINTS\Altium_Footprint_Lib.PcbLib; Height: 0.40MM; Library Path: Y:\MIS_DATABASE\Library\ALTIUM_TOOL\SCHEMATICS_PARTS\MS_DISCRETE_Library.schlib; Mfr_name: PANASONIC-ECG; Mfr_part_number: ERJ-2GEJ221X; Mistral Part No: 110009030506-R; Package: 0402; Part_type: RESISTORS\FIXED; Project: RED EYE; RoHS: RoHS; Temperature: -55°C+155°C; Tolerance: 5%; Voltage: NA; Wattage: 1/10W; Weight: 0.8mg; Datasheet: Y:\MIS_DATABASE\DATASHEETS\RESISTORS\PAN-ERJSER_NOV17.PDF
TP35 TP46 TP48 TP52 TP88 TP90 = TESTPOINT: TESTPOINT CIR 20 SMD; Chkd/date: SHREESHAIL/171006; Crtd /date: MAZHAR/171006; Custom_Duty: NA; Customs_HS_Code: NA; Distributor_name: NA; Distributor_part_number: NA; Footprint Path: Y:\MIS_DATABASE\Library\ALTIUM_TOOL\PCB_FOOTPRINTS\Altium_Footprint_Lib.PcbLib; Height: NA; Library Path: Y:\MIS_DATABASE\Library\ALTIUM_TOOL\SCHEMATICS_PARTS\MS_DISCRETE_Library.schlib; MECHANICAL 3D STEP FILE: NA; Mfr_name: LOCAL; Mistral Part No: NA; Package: SMD; Project: BT MODULE_CSRBC04; RoHS: NA; Temperature: NA; Tolerance: NA; Voltage: NA; Wattage: NA; Weight: NA; Datasheet: NA
TP69 = TESTPOINT: TESTPOINT CIR 20 SMD; Chkd/date: SHREESHAIL/171006; Crtd /date: MAZHAR/171006; Custom_Duty: NA; Customs_HS_Code: NA; Distributor_name: NA; Distributor_part_number: NA; Footprint Path: Y:\MIS_DATABASE\Library\ALTIUM_TOOL\PCB_FOOTPRINTS\Altium_Footprint_Lib.PcbLib; Height: NA; Library Path: Y:\MIS_DATABASE\Library\ALTIUM_TOOL\SCHEMATICS_PARTS\MS_DISCRETE_Library.schlib; MECHANICAL 3D STEP FILE: NA; Manufacturer: LOCAL; Mfr_name: LOCAL; Mistral Part No: NA; Package: SMD; Project: BT MODULE_CSRBC04; RoHS: NA; Temperature: NA; Tolerance: NA; Voltage: NA; Wattage: NA; Weight: NA; Datasheet: NA
U16 = TLV7103318D_WSON6: IC 200mA 3.3V/1.8V LOW IQ LDO REGULATOR WSON6; Alternate_mfr_name_A: TEXAS INSTRUMENTS; Alternate_mfr_part_number_A: TLV7103318DSER; Chkd/date: MANIRAJA/091018; Crtd /date: MANIRAJA/091018; Custom_Duty: 15%; Customs_HS_Code: 85423100; Distributor_name: DIGIKEY; Distributor_name_A: DIGIKEY; Distributor_part_number: 296-40641-1-ND; Distributor_part_number_A: 296-46453-1-ND; Footprint Path: Y:\MIS_DATABASE\Library\ALTIUM_TOOL\PCB_FOOTPRINTS\Altium_Footprint_Lib.PcbLib; Height: 0.80MM; Library Path: Y:\MIS_DATABASE\Library\ALTIUM_TOOL\SCHEMATICS_PARTS\MS_MISCPOWER_Library.schlib; Mfr_name: TEXAS INSTRUMENTS; Mistral Part No: 142018100013-R; Package: WSON6; Part_type: ICS\POWER\VOLTAGE REGULATOR; Project: TI_J7ES_EVM_SOM; RoHS: RoHS; Temperature: -40°C+125°C; Tolerance: NA; Voltage: NA; Wattage: NA; Weight: 9.7mg; Datasheet: Y:\MIS_DATABASE\DATASHEETS\ICS\POWER\TLV710331X-Q1.PDF
U19 = SN74LVC1G08DBVRE4_SOT23-5: IC SINGLE 2-INPUT POSITIVE AND GATE SOT23-5; Chkd/date: SUHAS/221010; Crtd /date: USMAN/151008; Custom_Duty: 15%; Customs_HS_Code: 85423100; Distributor_name: DIGIKEY; Distributor_part_number: SN74LVC1G08DBVRE4-ND; Height: 1.45MM; Mfr_name: TEXAS INSTRUMENTS; Mistral Part No: 141009060026-R; Part_type: ICS\DIGITAL\GATES; Project: KHAN_MAIN; RoHS: Sb/ Br FREE; Temperature: -40°C+85°C; Datasheet: Y:\MIS_DATABASE\DATASHEETS\ICS\DIGITAL\GATES\SN74LVC1G08.PDF
U42 = TPS22965DSGT_WSON8: IC 5.7V 6A 1-CHANNEL 16mE ON-RESISTANCE LOAD SWITCH WSON8; Chkd/date: MANIRAJA/080817; Crtd /date: VASANTHA/280714; Custom_Duty: 15%; Customs_HS_Code: 85423100; Distributor_name: DIGIKEY; Distributor_part_number: 296-34943-1-ND; Footprint Path: Y:\MIS_DATABASE\Library\ALTIUM_TOOL\PCB_FOOTPRINTS\Altium_Footprint_Lib.PcbLib; Height: 0.80MM; Library Path: Y:\MIS_DATABASE\Library\ALTIUM_TOOL\SCHEMATICS_PARTS\MS_MISCPOWER_Library.schlib; Mfr_name: TEXAS INSTRUMENTS; Mistral Part No: 142014070020-R; Package: WSON8; Part_type: ICS\POWER\DRIVER; Project: DC_MIST_DIGITAL CARD; RoHS: RoHS; Temperature: -40°C+105°C; Tolerance: NA; Voltage: NA; Wattage: NA; Weight: 11mg; Datasheet: Y:\MIS_DATABASE\DATASHEETS\ICS\POWER\TPS22965-SER.PDF
U46 = TLV75801P_SOT23-5: IC 500mA ADJ LDO REGULATOR SOT23-5; Chkd/date: PRAVEEN/220922; Crtd /date: PRAVEEN/220922; Custom_Duty: 15%; Customs_HS_Code: 85423100; Distributor_name: DIGIKEY; Distributor_part_number: 296-TLV75801PDBVTCT-ND; Footprint Path: Y:\MIS_DATABASE\Library\ALTIUM_TOOL\PCB_FOOTPRINTS\Altium_Footprint_Lib.PcbLib; Height: 1.45MM; Library Path: Y:\MIS_DATABASE\Library\ALTIUM_TOOL\SCHEMATICS_PARTS\MS_MISCPOWER_Library.schlib; Mfr_name: TEXAS INSTRUMENTS; Mistral Part No: 142022090041-R; Package: SOT23-5; Part_type: ICS\POWER\VOLTAGE REGULATOR; Project: TRINETRA MISTRAL-DF; RoHS: RoHS; Temperature: -40°C+125°C; Tolerance: NA; Voltage: NA; Wattage: NA; Weight: NA; Datasheet: Y:\MIS_DATABASE\DATASHEETS\ICS\POWER\TLV75801PXXX.PDF
U59 = TPS7A21_SON8: IC 500MA, LOW-NOISE, LOW-IQ, HIGH-PSRR LDO SON8; Chkd/date: PRADEEP/010424; Crtd /date: TAMILARASU/010424; Custom_Duty: 15%; Customs_HS_Code: 85423100; Distributor_name: DIGIKEY; Distributor_part_number: 296-TPS7A2118PQWDRBRQ1CT-ND; Footprint Path: Y:\MIS_DATABASE\Library\ALTIUM_TOOL\PCB_FOOTPRINTS\Altium_Footprint_Lib.PcbLib; Height: 1.00MM; Library Path: Y:\MIS_DATABASE\Library\ALTIUM_TOOL\SCHEMATICS_PARTS\MS_MISCINTERFACE_Library.schlib; Mfr_name: TEXAS INSTRUMENTS; Mistral Part No: 140124040001-R; Package: SON8; Part_type: ICS\INTERFACE; Project: AM62L_EVM; RoHS: RoHS; Temperature: -40°C+150°C; Tolerance: NA; Voltage: NA; Wattage: NA; Weight: NA; Datasheet: Y:\MIS_DATABASE\DATASHEETS\ICS\DIGITAL\BUSTRANSCEIVER\TPS7A2118PQWDRBRQ1.PDF
U33 U35 U89 = SN74LVC1G126DBVR_SOT23-5: IC SINGLE BUS BUFFER GATE WITH 3-STATE O/P SOT23-5; Chkd/date: MANIRAJA/130519; Crtd /date: MAZHAR/301106; Custom_Duty: 15%; Customs_HS_Code: 85423100; Distributor_name: DIGIKEY; Distributor_part_number: 296-11605-1-ND; Footprint Path: Y:\MIS_DATABASE\Library\ALTIUM_TOOL\PCB_FOOTPRINTS\Altium_Footprint_Lib.PcbLib; Height: 1.45MM; Library Path: Y:\MIS_DATABASE\Library\ALTIUM_TOOL\SCHEMATICS_PARTS\MS_GATE_Library.schlib; Mfr_name: TEXAS INSTRUMENTS; Mistral Part No: 141009030232-R; Package: SOT23-5; Part_type: ICS\DIGITAL\GATES; Project: PMP LCD BOARD; RoHS: RoHS; Temperature: -40°C+125°C; Tolerance: NA; Voltage: NA; Wattage: NA; Weight: 6.3mg; Datasheet: Y:\MIS_DATABASE\DATASHEETS\ICS\DIGITAL\GATES\SN74LVC1G126XXX.PDF
C189 C268 = CAP: CAP CERAMIC 0.01uF 25V 10% X5R AUTO 0201; Chkd/date: MANIRAJA/311221; Crtd /date: ALVY/301221; Custom_Duty: 15%; Customs_HS_Code: 85322990; Distributor_name: MOUSER; Distributor_part_number: 81-GRT033R61E103KE1D; Footprint Path: Y:\MIS_DATABASE\Library\ALTIUM_TOOL\PCB_FOOTPRINTS\Altium_Footprint_Lib.PcbLib; Height: 0.33MM; Library Path: Y:\MIS_DATABASE\Library\ALTIUM_TOOL\SCHEMATICS_PARTS\MS_DISCRETE_Library.schlib; Mfr_name: MURATA; Mfr_part_number: GRT033R61E103KE01D; Mistral Part No: 120021120019-R; Package: 0201; Part_type: CAPACITORS\CERAMIC; Project: AM62Q_SKEVM_BRD; RoHS: RoHS; Temperature: -55°C+85°C; Tolerance: 10%; Voltage: 25V; Wattage: NA; Weight: 0.33mg; Datasheet: Y:\MIS_DATABASE\DATASHEETS\CAPACITORS\GRT033R61E103KE01.PDF
J20 = HEADER_2X1: CON HDR 1X2 2.54MM PITCH ST TH; Chkd/date: MANIRAJA/031018; Crtd /date: ALVY/031018; Custom_Duty: 24%; Customs_HS_Code: 85369090; Distributor_name: DIGIKEY; Distributor_part_number: 732-5315-ND; Footprint Path: Y:\MIS_DATABASE\Library\ALTIUM_TOOL\PCB_FOOTPRINTS\Altium_Footprint_Lib.PcbLib; Height: 8.54MM; Library Path: Y:\MIS_DATABASE\Library\ALTIUM_TOOL\SCHEMATICS_PARTS\MS_CONNECTOR_Library.schlib; Mfr_name: WURTH ELECTRONICS; Mfr_part_number: 61300211121; Mistral Part No: 150018100003-R; Package: THRU-HOLE; Part_type: CONNECTOR\HEADERS; Project: ALPINE_EVM; RoHS: RoHS; Temperature: -40°C+105°C; Tolerance: NA; Voltage: NA; Wattage: NA; Weight: 120mg; Datasheet: Y:\MIS_DATABASE\DATASHEETS\CONNECTORS\6130XXX.PDF
U44 U63 = TMP100NA_3K_SOT23-6: IC TEMPERATURE SENSOR WITH I2C AND SMBUS INTERFACE SOT23-6; Chkd/date: MANIRAJA/290817; Crtd /date: MANIRAJA/290817; Custom_Duty: 15%; Customs_HS_Code: 85423100; Distributor_name: DIGIKEY; Distributor_part_number: 296-26833-1-ND; Height: 1.45MM; Library Ref: TMP100NA/3K_SOT23-6; Mfr_name: TEXAS INSTRUMENTS; Mistral Part No: 141017080030-R; Package: SOT23-6; Part_type: ICS\DIGITAL\PERIPHERAL; Project: TI_MAXIE_CPB; RoHS: RoHS; Temperature: -55°C+125°C; Tolerance: NA; Voltage: NA; Wattage: NA; Weight: 120mg; Datasheet: Y:\MIS_DATABASE\DATASHEETS\ICS\DIGITAL\PERIPHERAL\TMP10XX.PDF
U70 = AT24C64D-MAHM-T_UDFN8: IC 1.7-3.6V 512Kb I2C COMPATIBLE SERIAL EEPROM UDFN8; Chkd/date: MANIRAJA/240919; Crtd /date: ALVY/240919; Custom_Duty: 15%; Customs_HS_Code: 85423100; Distributor_name: DIGIKEY; Distributor_part_number: AT24C512C-MAHM-TCT-ND; Footprint Path: Y:\MIS_DATABASE\Library\ALTIUM_TOOL\PCB_FOOTPRINTS\Altium_Footprint_Lib.PcbLib; Height: 0.60MM; Library Path: Y:\MIS_DATABASE\Library\ALTIUM_TOOL\SCHEMATICS_PARTS\MS_MISCMEMORY_Library.schlib; Mfr_name: MICROCHIP; Mistral Part No: 141119090004-R; Package: UDFN8; Part_type: ICS\DIGITAL\MEMORY; Project: HAL_3U-T1042-SBC; RoHS: RoHS; Temperature: -40°C+85°C; Tolerance: NA; Voltage: NA; Wattage: NA; Weight: 9.5mg; Datasheet: Y:\MIS_DATABASE\DATASHEETS\ICS\MEMORY\AT24C512C.PDF
R310 R311 R331 R335 R539 R540 R571 R572 R584 R585 R599 R600 = RESISTOR: RES 0E 1/16W JUMPER 0402; Chkd/date: VASANTHA/201216; Crtd /date: MUDDU/190810; Custom_Duty: 15%; Customs_HS_Code: 85332119; Distributor_name: DIGIKEY; Distributor_part_number: 541-0.0JCT-ND; Footprint Path: Y:\MIS_DATABASE\Library\ALTIUM_TOOL\PCB_FOOTPRINTS\Altium_Footprint_Lib.PcbLib; Height: 0.40MM; Library Path: Y:\MIS_DATABASE\Library\ALTIUM_TOOL\SCHEMATICS_PARTS\MS_DISCRETE_Library.schlib; Mfr_name: VISHAY; Mfr_part_number: CRCW04020000Z0ED; Mistral Part No: 110010080019-R; Package: 0402; Part_type: RESISTORS\FIXED; Project: PB_BUGBASE; RoHS: RoHS; Temperature: -55°C+155°C; Tolerance: NA; Voltage: NA; Wattage: 1/16W; Weight: 0.65mg; Datasheet: Y:\MIS_DATABASE\DATASHEETS\RESISTORS\CRCW0603.PDF
U91 U114 U116 U118 U122 U124 = INA226AIDGS_MSOP10: IC 85V 20BIT POWER/ENERGY/CHARGE MONITOR WITH I2C INTERFACE VSSOP10; Chkd/date: MANIRAJA/041021; Crtd /date: ALVY/011021; Custom_Duty: 15%; Customs_HS_Code: 85423100; Distributor_name: DIGIKEY; Distributor_part_number: 296-INA228AIDGSRCT-ND; Footprint Path: Y:\MIS_DATABASE\Library\ALTIUM_TOOL\PCB_FOOTPRINTS\Altium_Footprint_Lib.PcbLib; Height: 1.10MM; Library Path: Y:\MIS_DATABASE\Library\ALTIUM_TOOL\SCHEMATICS_PARTS\MS_MISCPOWER_Library.schlib; Mfr_name: TEXAS INSTRUMENTS; Mistral Part No: 142021100003-R; Package: VSSOP10; Part_type: ICS\POWER\MANAGEMENT; Project: ENEKOM_SMART SENSOR SYSTEM; RoHS: RoHS; Temperature: -40°C+125°C; Tolerance: NA; Voltage: NA; Wattage: NA; Weight: NA; Datasheet: Y:\MIS_DATABASE\DATASHEETS\ICS\POWER\INA228A.PDF

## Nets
DGND: C108.2 C115.2 C119.2 C123.2 C166.2 C173.2 C189.1 C191.1 C193.2 C197.2 C199.1 C204.2 C207.2 C224.2 C247.1 C251.1 C255.2 C268.1 C298.2 C418.2 C427.2 C499.2 C525.2 C560.2 C598.2 C601.2 C604.2 J20.2 LD6.1(CATHODE) R71.2 R103.1 R226.2 R245.1 R247.2 R258.2 R320.2 R369.2 R370.2 R488.2 U16.4(GND) U19.3(GND) U33.3(GND) U35.3(GND) U42.5(GND) U42.9(EP) U44.2(GND) U46.2(GND) U59.4(GND) U59.9(EP) U63.2(GND) U70.4(GND) U70.9(EPAD) U89.3(GND) U91.2(A0) U91.7(GND) U114.1(A1) U114.2(A0) U114.7(GND) U116.1(A1) U116.7(GND) U118.7(GND) U122.7(GND) U124.7(GND) ; also on sheet 1 2 3 4 5 6 7 8 9 10 12 13 19 20 21 22 31 32 33 34 35 36 37 38 39 40 41 42 43 44 45 46 47 48 49 50 51 52 53 54 55 56 57 58
DVDD1V8_ALERT: R305.1 U124.3(ALERT) ; also on sheet 19
DVDD3V3: R244.1 ; also on sheet 33
DVDD3V3_ALERT: R505.1 U91.3(ALERT) ; also on sheet 19
VCC1V1_N: R599.2 ; also on sheet 33
VCC1V1_P: R600.2 ; also on sheet 33
VCC1V8_SYS_N: R335.2 ; also on sheet 33
VCC1V8_SYS_P: R331.2 ; also on sheet 33
VCC_1V8_IOVDD: C166.1 C173.1 C418.1 R162.1 U33.5(VCC) U35.5(VCC) U89.5(VCC) ; also on sheet 5 56
VCC_3V3_MAIN: C197.1 C199.2 C204.1 C255.1 R240.1 U42.1(VIN1) U42.2(VIN2) U42.4(VBIAS) U46.1(IN) U59.8(IN) ; also on sheet 2 13 32 33 43
VCC_3V3_SYS: C123.1 C189.2 C191.2 C268.2 C298.1 C427.1 C525.1 C560.1 C598.1 C601.1 C604.1 R91.2 R251.3 R324.2 R325.2 R339.1 R368.1 R597.2 R617.2 TP48.1(TP) U19.5(VCC) U42.7(VOUT1) U42.8(VOUT2) U44.4(V+) U63.4(V+) U70.8(VCC) U91.6(VS) U114.6(VS) U116.2(A0) U116.6(VS) U118.2(A0) U118.6(VS) U122.1(A1) U122.6(VS) U124.1(A1) U124.2(A0) U124.6(VS) ; also on sheet 1 2 3 6 10 19 20 22 31 33 37 38 40 41 42 45 46 48 49 50 51 52 53 54 55 56 57 58
VCC_3V3_SYS_EN: R244.2 R245.2 U42.3(ON)
VCC_3V3_SYS_N: R251.1 R539.2
VCC_3V3_SYS_P: R251.4 R540.2
VCC_5V0: C115.1 C119.1 U16.2(IN) ; also on sheet 6 31 32 34 51 52 54
VCC_CORE_N: R572.2 ; also on sheet 33
VCC_CORE_P: R571.2 ; also on sheet 33
VCC_SDIO: C108.1 R77.1 U16.5(OUT2) U16.6(OUT1)
VDD_0V85_N: R585.2 ; also on sheet 33
VDD_0V85_P: R584.2 ; also on sheet 33
VDD_1V8_N: R311.2 ; also on sheet 33
VDD_1V8_P: R310.2 ; also on sheet 33
VDD_CANUART: C224.1 C499.1 R257.2 TP52.1(TP) ; also on sheet 34
VDD_CORE_ALERT: R586.1 U114.3(ALERT) ; also on sheet 19
VDD_CORE_N: C524.2 R572.1 U114.8(VBUS) U114.9(IN-) ; also on sheet 19
VDD_CORE_P: C524.1 R571.1 U114.10(IN+) ; also on sheet 19
VDD_LPDDR4_ALERT: R619.1 U122.3(ALERT) ; also on sheet 19
VDD_LPDDR4_N: C600.2 R599.1 U122.8(VBUS) U122.9(IN-) ; also on sheet 19
VDD_LPDDR4_P: C600.1 R600.1 U122.10(IN+) ; also on sheet 19
VDDA_1V8_ALERT: R608.1 U118.3(ALERT) ; also on sheet 19
VDDA_1V8_N: C597.2 R311.1 U118.8(VBUS) U118.9(IN-) ; also on sheet 19
VDDA_1V8_P: C597.1 R310.1 U118.10(IN+) ; also on sheet 19
VDDR_CORE_ALERT: R596.1 U116.3(ALERT) ; also on sheet 19
VDDR_CORE_N: C559.2 R585.1 U116.8(VBUS) U116.9(IN-) ; also on sheet 19
VDDR_CORE_P: C559.1 R584.1 U116.10(IN+) ; also on sheet 19
VDDSHV_SDIO: R71.1 R77.2 TP35.1(TP) ; also on sheet 13 38
VDDSHV_SDIO_EN: U16.3(EN2) U19.2(B) ; also on sheet 38
CPLD/EXP2_McASP2_ACLKR: U33.2(A) ; also on sheet 6 11
CPLD/EXP2_McASP2_AXR14: R486.2 ; also on sheet 6 11
CPLD/EXP2_McASP2_AXR15: R165.2 ; also on sheet 6 11
EEPROM_A0: R370.1 U70.1(A0)
EEPROM_A1: R369.1 U70.2(A1)
EEPROM_A2: R368.2 U70.3(A2)
EEPROM_WP: J20.1 R617.1 U70.7(WP)
INA_ALERT: R305.2 R505.2 R586.2 R596.2 R597.1 R608.2 R619.2 TP46.1(TP)
PCM6240_BUF_EN: R687.1 ; also on sheet 22
PCM6240_BUF_IO_EN: R688.1 ; also on sheet 55
PCM6240_McASP2_ACLKR: R163.2 ; also on sheet 5 56
PCM6240_McASP2_AXR14: U89.2(A) ; also on sheet 5 56
PCM6240_McASP2_AXR15: U35.2(A) ; also on sheet 5
SoC_DVDD1V8_N: C603.2 R335.1 U124.8(VBUS) U124.9(IN-) ; also on sheet 19
SoC_DVDD1V8_P: C603.1 R331.1 U124.10(IN+) ; also on sheet 19
SoC_DVDD3V3: R251.2 ; also on sheet 13 34 35
SoC_DVDD3V3_N: C428.2 R539.1 U91.8(VBUS) U91.9(IN-) ; also on sheet 19
SoC_DVDD3V3_P: C428.1 R540.1 U91.10(IN+) ; also on sheet 19
SoC_I2C0_SCL: R332.1 U44.1(SCL) ; also on sheet 1 3 20 22 40 41 50 55
SoC_I2C0_SCL_R1: R332.2 TP88.1(TP) U63.1(SCL) U70.6(SCL) U91.1(A1) U91.5(SCL) U114.5(SCL) U116.5(SCL) U118.1(A1) U118.5(SCL) U122.2(A0) U122.5(SCL) U124.5(SCL) ; also on sheet 19 31
SoC_I2C0_SDA: R350.1 U44.6(SDA) ; also on sheet 1 3 20 22 40 41 50 55
SoC_I2C0_SDA_R1: R350.2 TP90.1(TP) U63.6(SDA) U70.5(SDA) U91.4(SDA) U114.4(SDA) U116.4(SDA) U118.4(SDA) U122.4(SDA) U124.4(SDA) ; also on sheet 19 31
TMP1_ADD0: R226.1 U44.5(ADD0)
TMP1_ADD1: R247.1 U44.3(ADD1)
TMP2_ADD0: R339.2 U63.5(ADD0)
TMP2_ADD1: R325.1 U63.3(ADD1)
VPP_1V8: R304.2 TP69.1(TP) ; also on sheet 13 34
VPP_EN: R319.1 ; also on sheet 55
VPP_SUPPLY: C247.2 C251.2 R304.1 U59.1(OUT)
VSEL_MMC1_SDIO: R103.2 U16.1(EN1) U19.4(Y)
VSEL_SD_SOC: R86.1 ; also on sheet 55
N26593111: R86.2 R91.1 U19.1(A)
N26594023: C193.1 U42.6(CT)
N27116765: R319.2 R320.1 U59.5(EN)
N27118410: R240.2 U46.3(EN)
N27118414: R255.2 R258.1 U46.4(FB)
N27118438: C207.1 R255.1 R257.1 U46.5(OUT)
N27170778: LD6.2(ANODE) R324.1
N27236897: R163.1 U33.4(Y)
N27236901: R486.1 U89.4(Y)
N27236905: R165.1 U35.4(Y)
N27237026: R488.1 R687.2 R688.2 U35.1(OE) U89.1(OE)
N27237106: R162.2 U33.1(OE)

Not connected (* = marked no-connect by the designer): U59 2(NC1)* 3(NC2)* 6(NC3)* 7(NC4)*

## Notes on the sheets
sheet 14
- SOC POWER SUPPLIES - LDOs
- 1.8V VPP (eFUSE), 0.5AMPS SUPPLY
- 3.3V/1.8V SD CARD IO SUPPLY
- SILK SCREEN : VPP_1V8
- VDD_CANUART(0.85V),0.5 AMPS SUPPLY
- Note: Resistor is to quickly discharge VDDSHV_SDIO voltage
  when switching from 3.3V to 1.8V
- VSEL_SD_SOC
- SD VOLTAGE
- HIGH(DEFAULT)
- 3.3V
- LOW
- 1.8V
- Modify R258 to 274K for 0.75V operation
  MPN : ERJ-2RKF2743X
  Default is 0.85V
- VCC_3V3_SYS LOAD SWITCH
- POWER INDICATION LED:
  VCC_3V3_SYS
- This pulldown provides
  a defined logic state
  when DVDD3V3
  is not sourced
sheet 15
- LINK TO DESIGN COLLATERALS
- https://e2e.ti.com/support/processors-group/processors/f/processors-forum/1285107/faq-am64x-
  am62x-am62ax-custom-board-hardware-design---collaterals-for-reference-during-schematic-design-and-schematics-review
- FAQs
sheet 16
- PCM6240 BUFFERS
sheet 17
- TEMPERATURE SENSORS
- I2C ADDRESS: 0x4B
- I2C ADDRESS: 0x4E
- CAD NOTE: PLACE CLOSE TO LPDDR4
- CAD NOTE: PLACE CLOSE TO SoC
- BOARD ID EEPROM
- I2C ADDRESS: 0X54
- Short with a
  Jumper to perform
  write operation
- PROC180E1
sheet 18
- CURRENT MONITORING DEVICES - 1
- SoC_DVDD1V8
- VDD_CORE
- I2C ADDRESS: 0x40
- I2C ADDRESS: 0x45
- VDDR_CORE
- VDDA_1V8
- I2C ADDRESS: 0x4D
- I2C ADDRESS: 0x41
- SoC_DVDD3V3
- VDD_LPDDR4
- I2C ADDRESS: 0x4C
- I2C ADDRESS: 0x47
- Note: The design supports current/voltage measurements
  using either INA228 or INA231.
  (Implemented via stacked PCB footprint).
- INA I2C SLAVE ADDRESS
- SLAVE
  ADDRESS
  (IN HEX)
- POWER SOURCE
- SUPPLY NET
- VCC_CORE
- VDD_CORE
- 40
- VCC_0V85
- VDDR_CORE
- 41
- VCC_3V3_SYS
- SoC_DVDD3V3
- 4C
- VCC_1V8
- SoC_DVDD1V8
- 45
- VDDA1V8
- VDDA_1V8
- 4D
- VCC1V1
- VDD_LPDDR4
- 47
- PROC180E2_SCH
